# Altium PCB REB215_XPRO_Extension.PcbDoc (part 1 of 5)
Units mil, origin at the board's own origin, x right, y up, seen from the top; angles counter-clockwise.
Board outline 4055.74 x 2606 mil, 6 copper layers (Top Layer LF-signals, Signal Layer 1, Internal Plane 1, Mid-1, Mid-2, Bottom Layer LF-signals), stack 58.434 mil thick; 278 components, 292 nets, 1282 pads, 1177 vias.
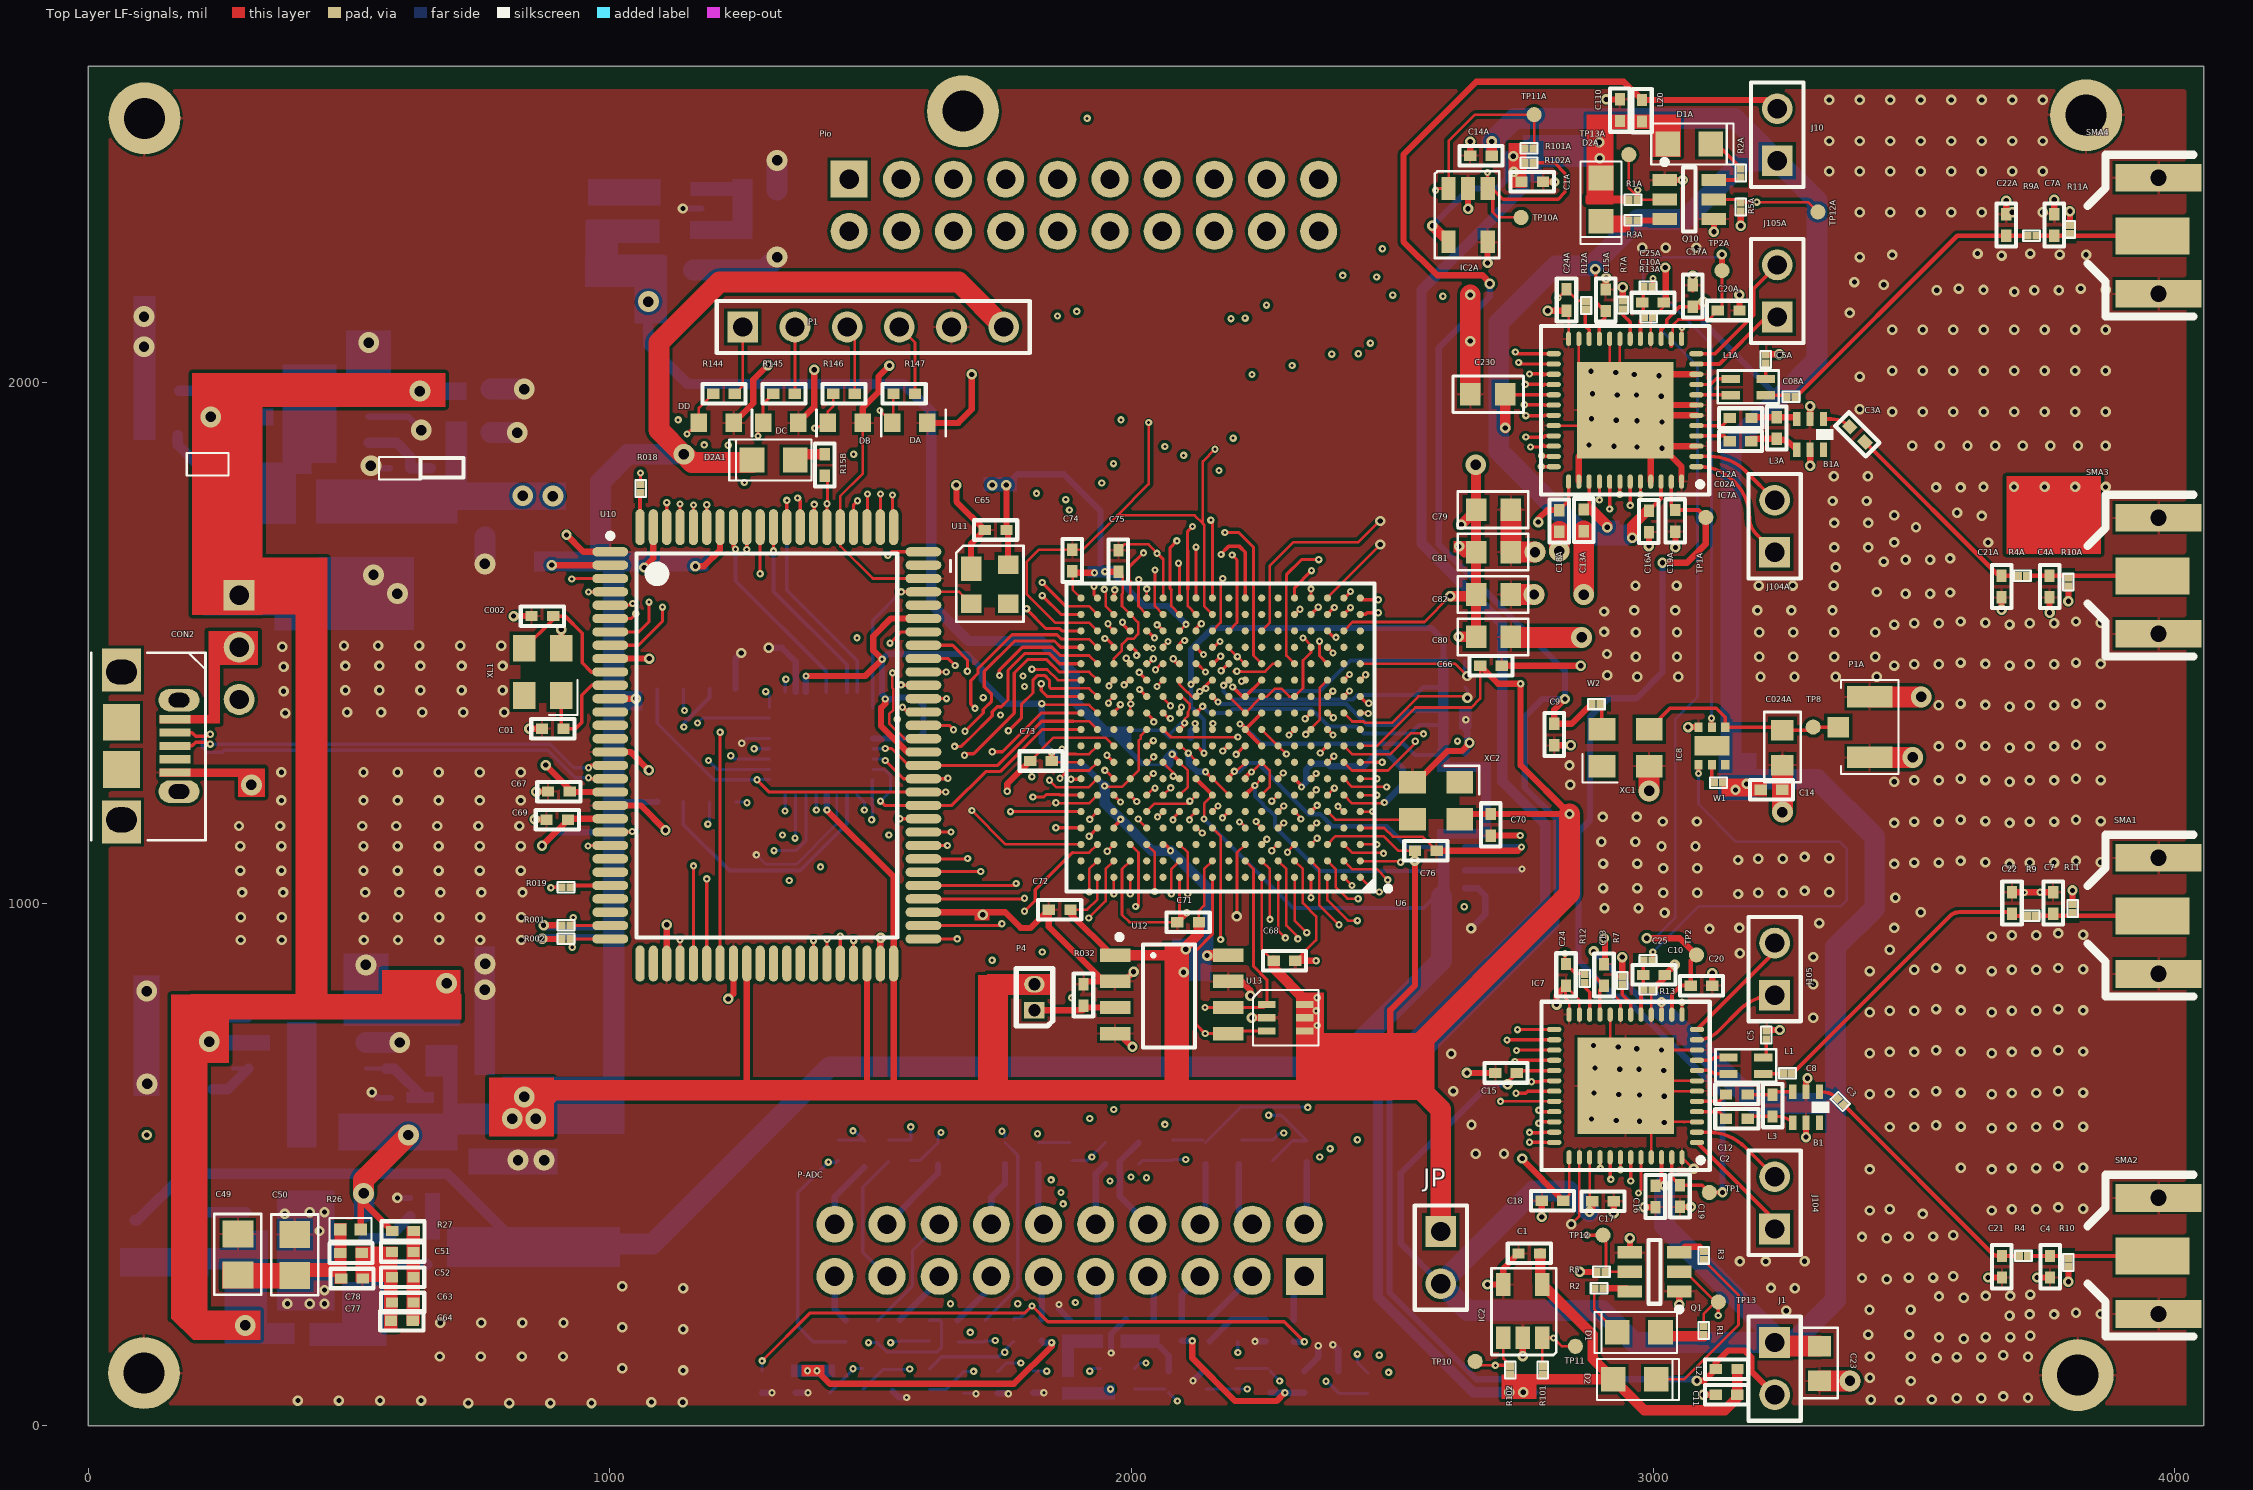
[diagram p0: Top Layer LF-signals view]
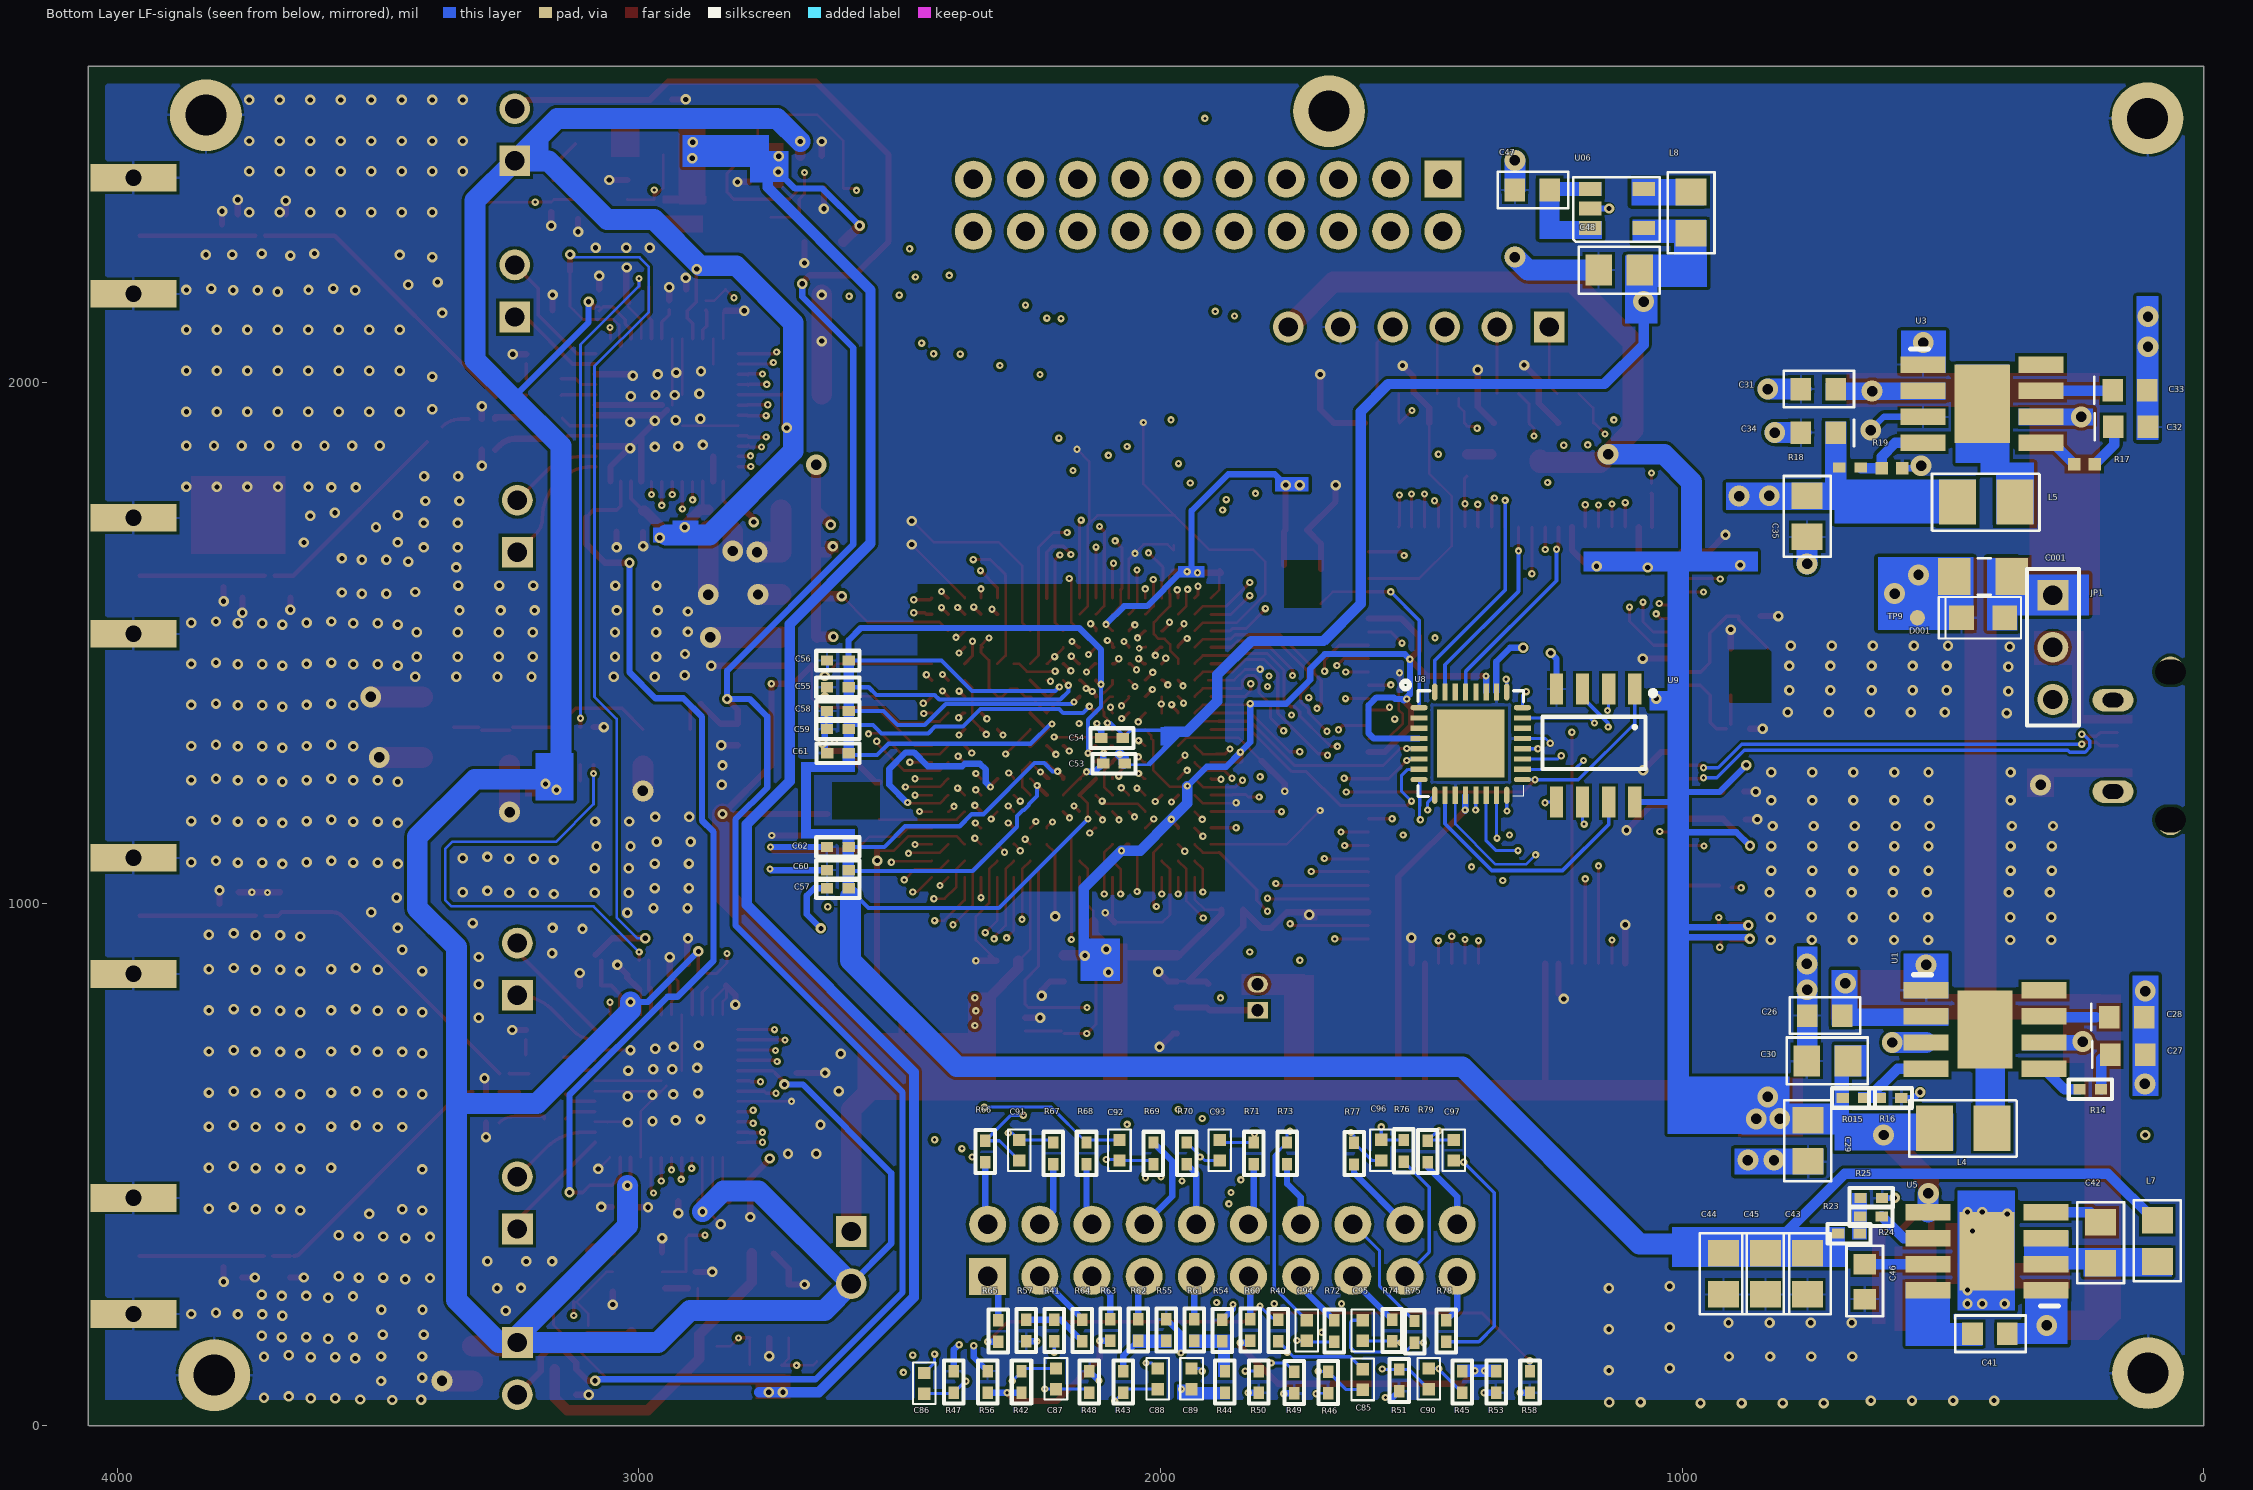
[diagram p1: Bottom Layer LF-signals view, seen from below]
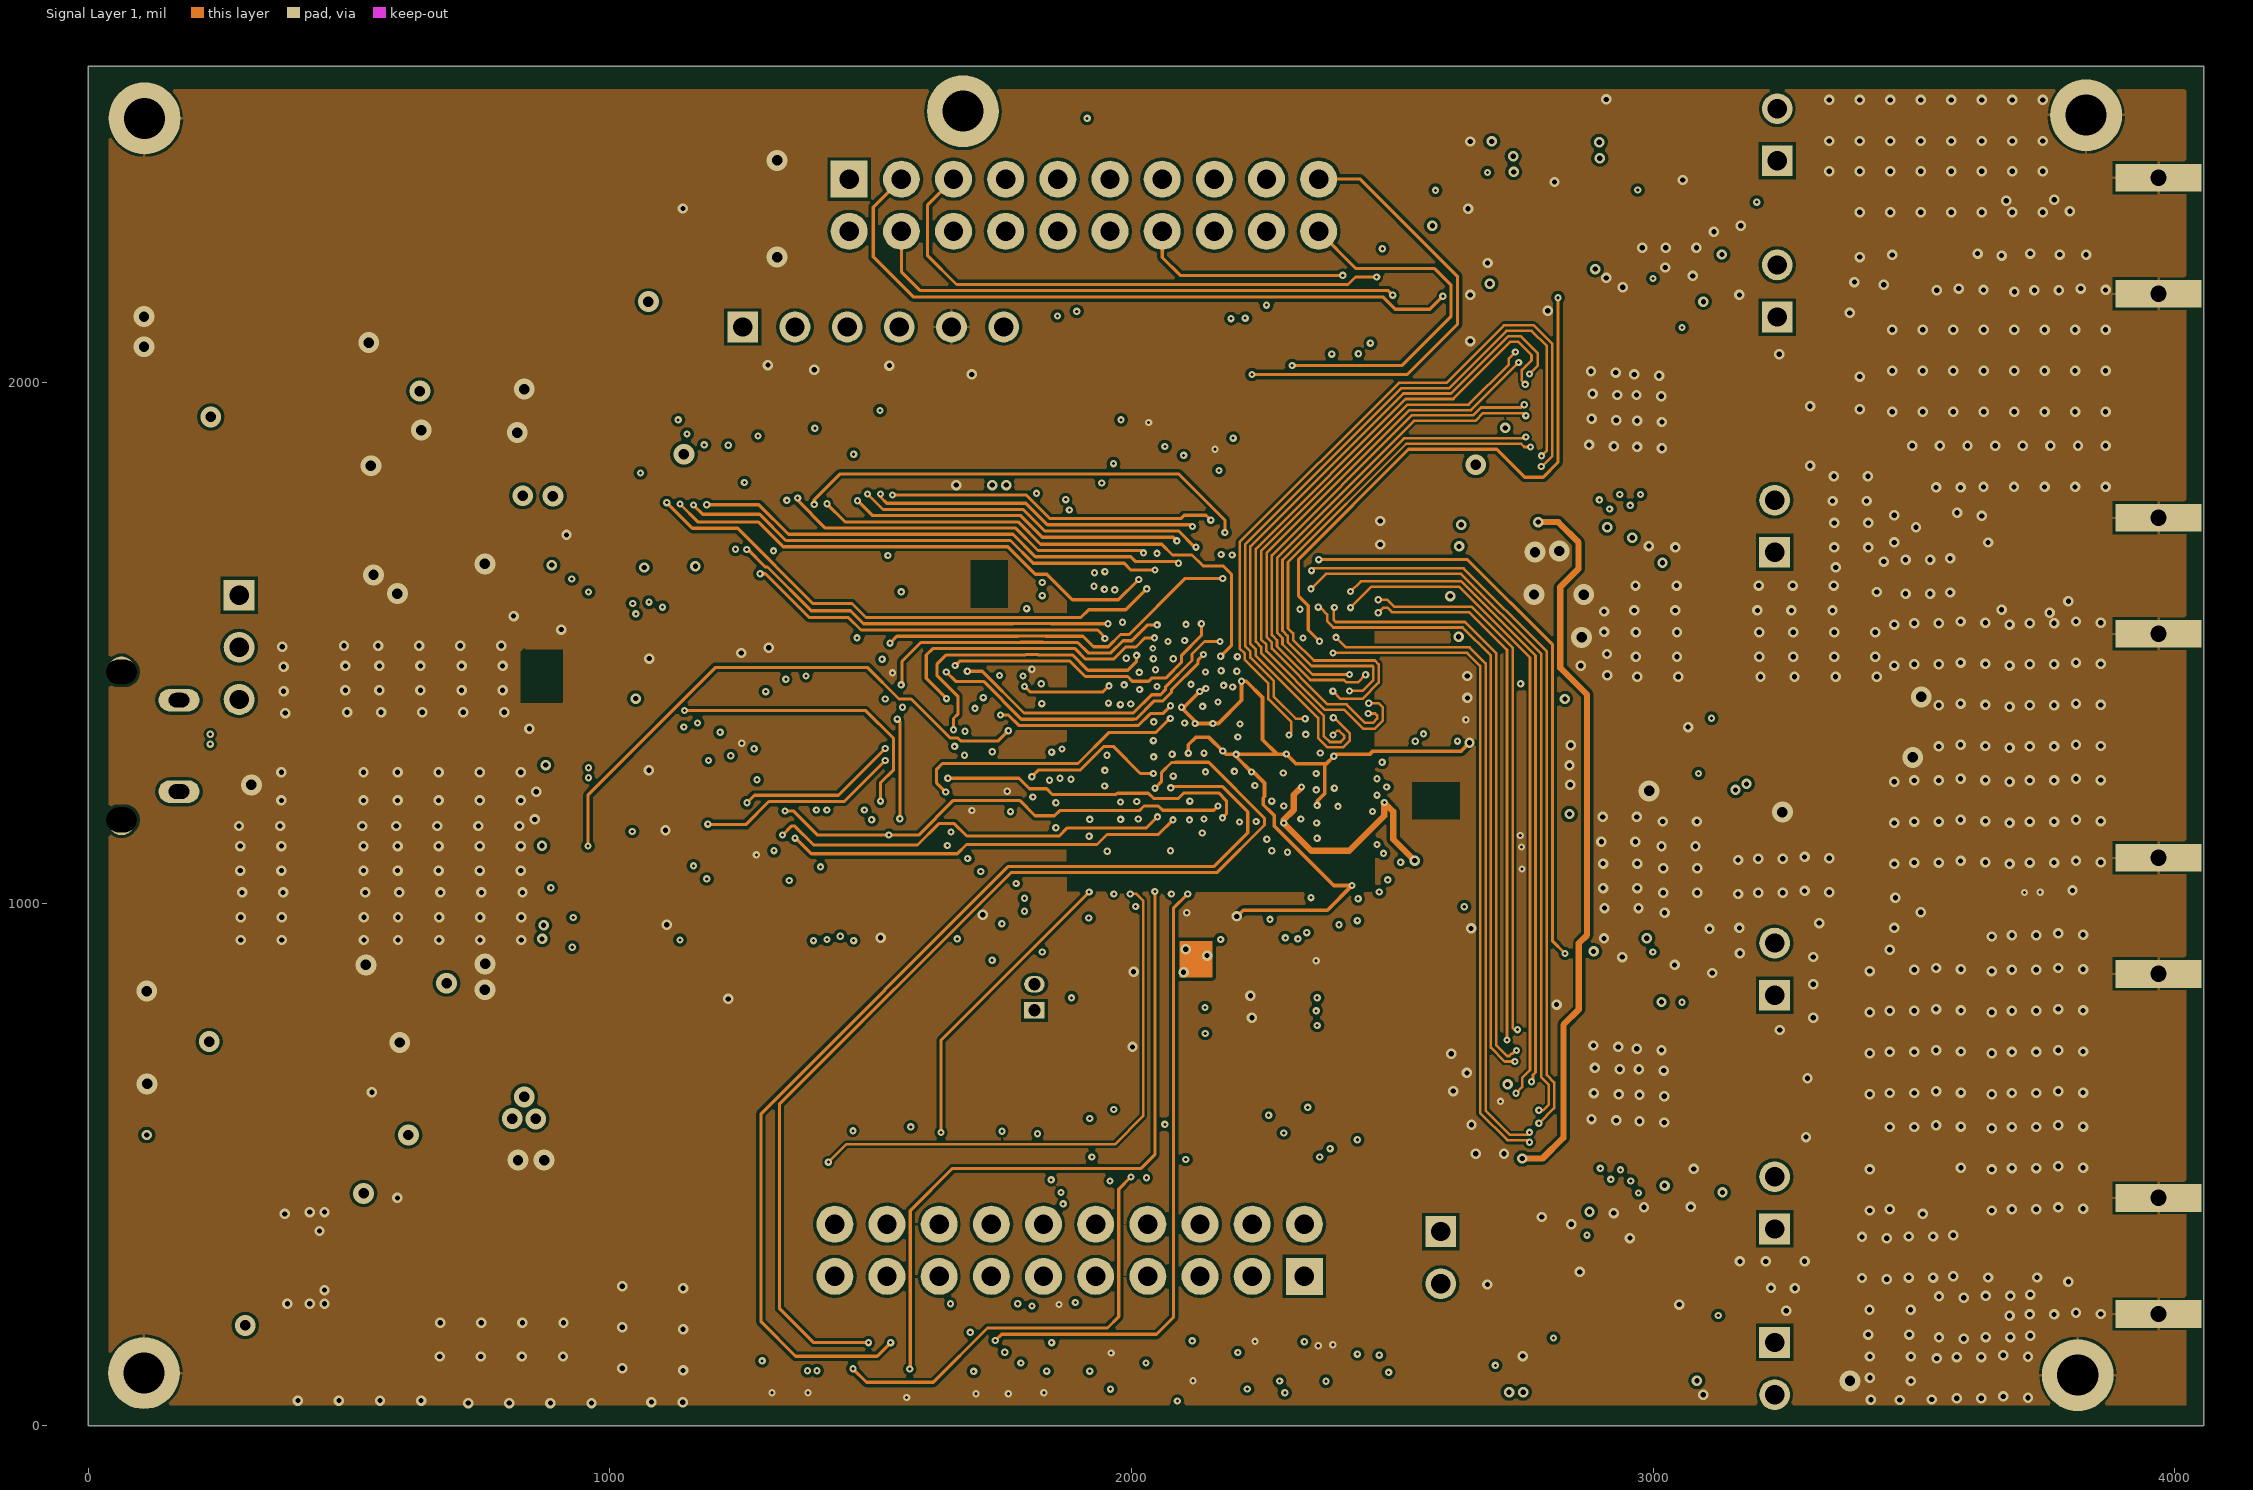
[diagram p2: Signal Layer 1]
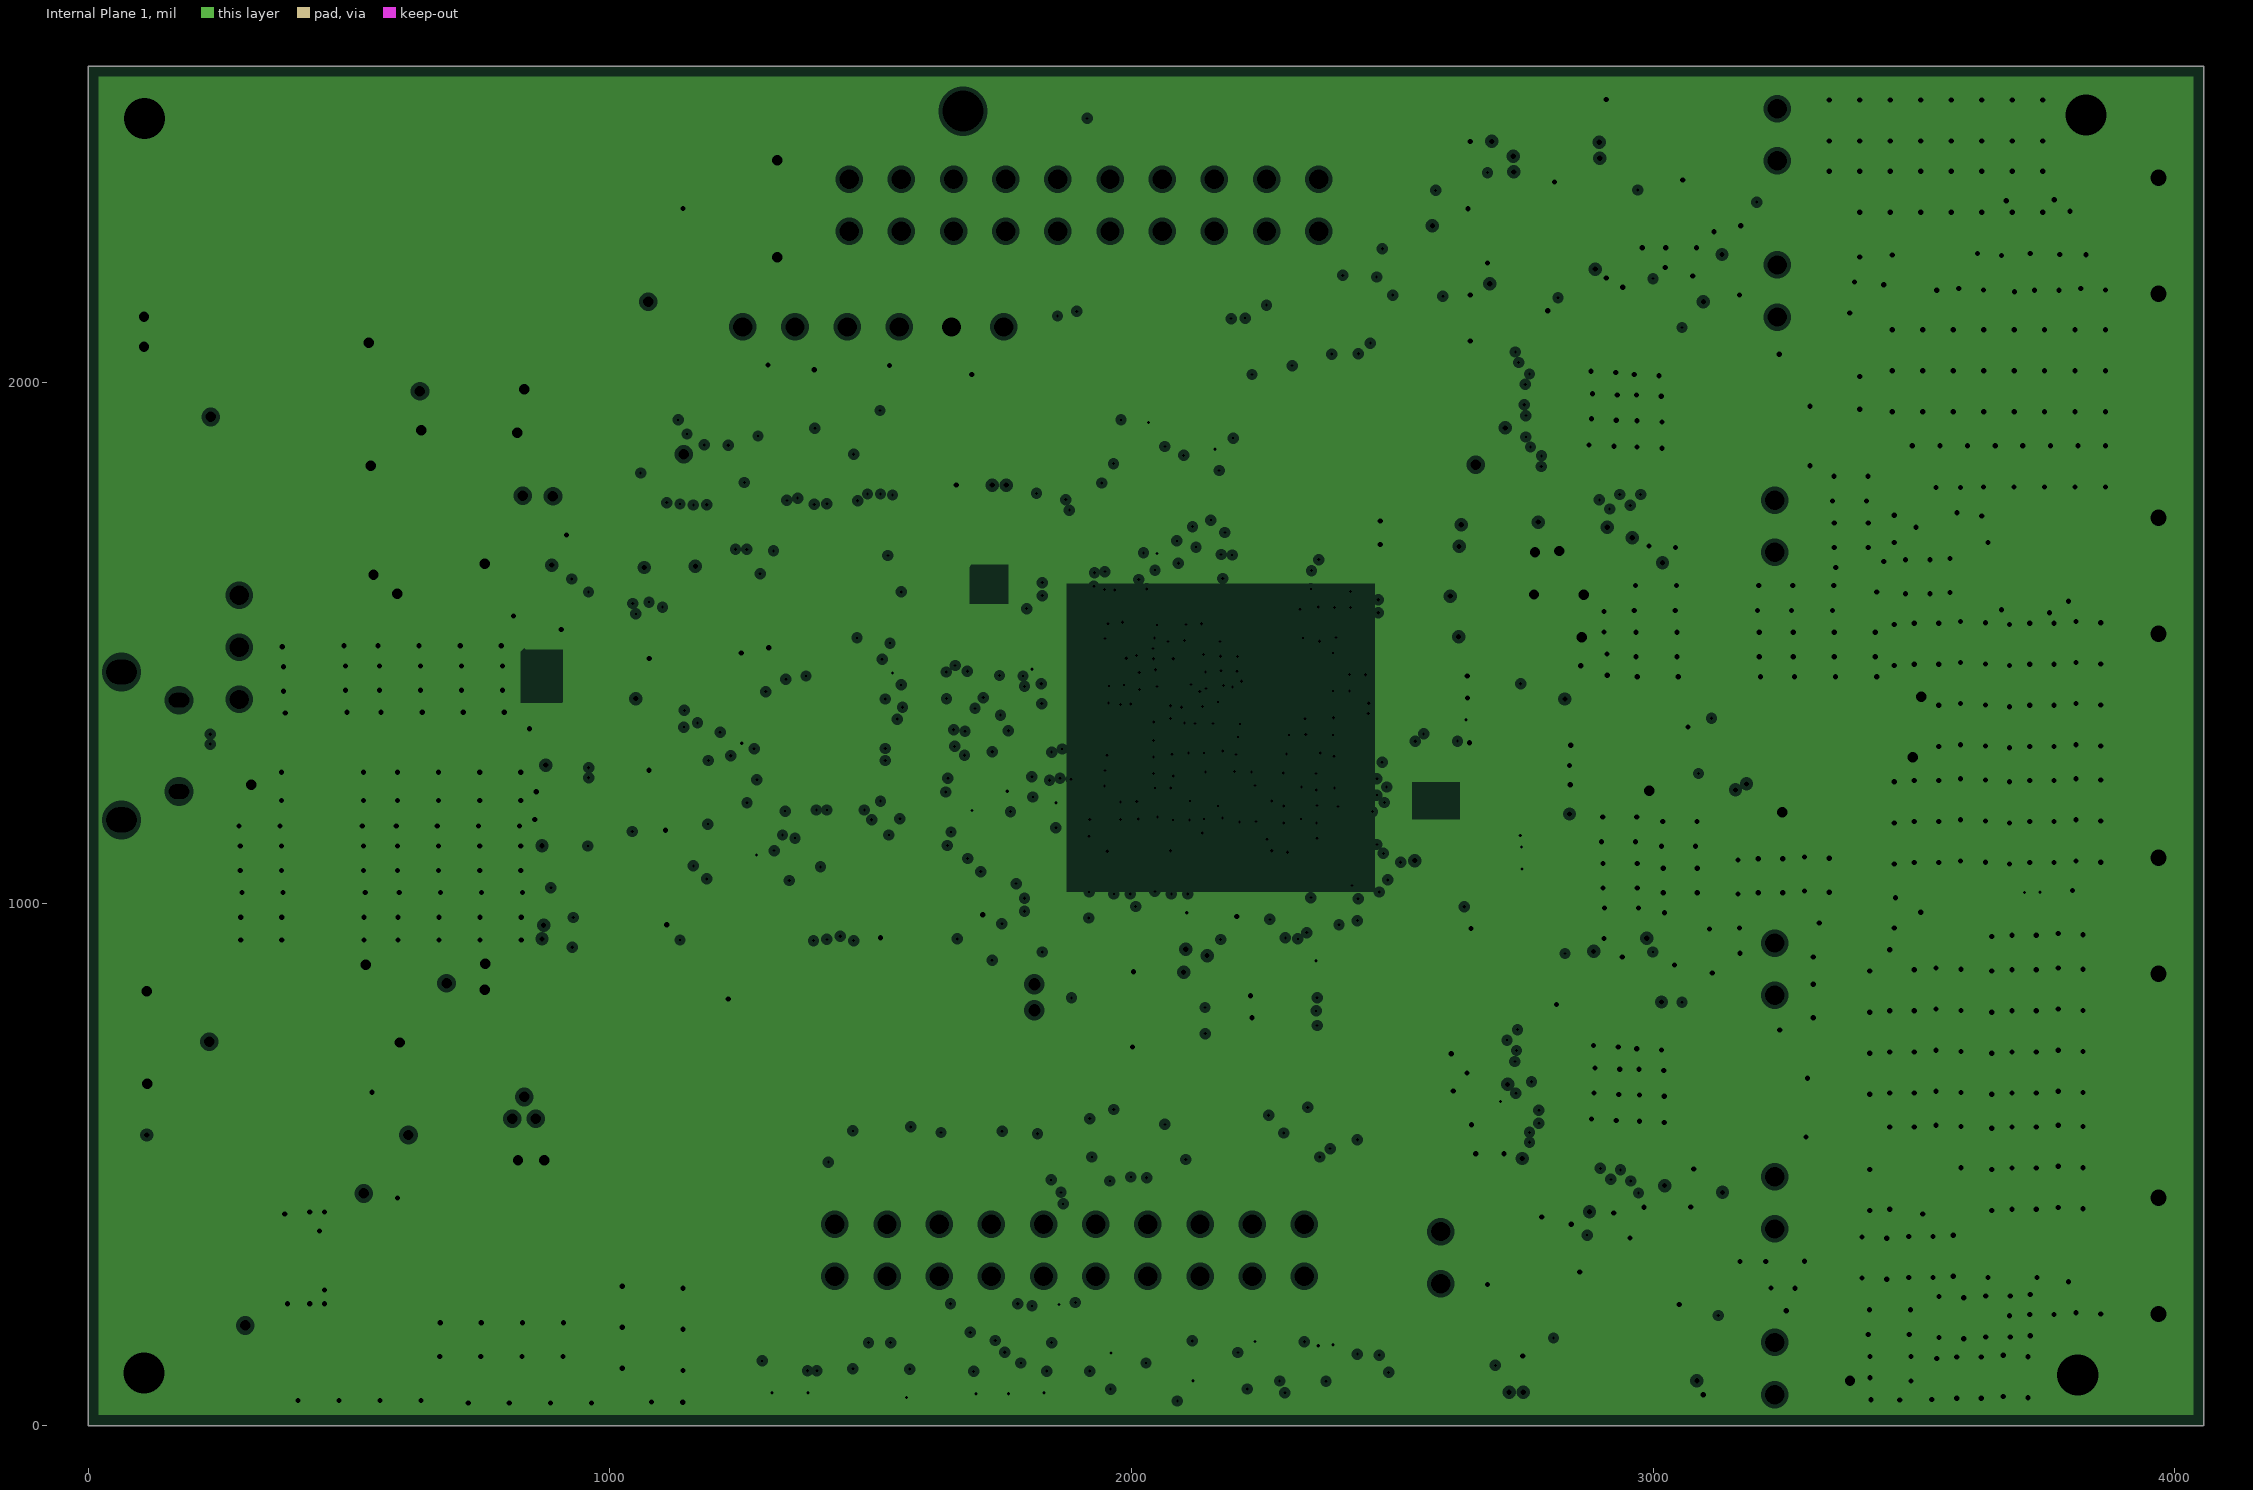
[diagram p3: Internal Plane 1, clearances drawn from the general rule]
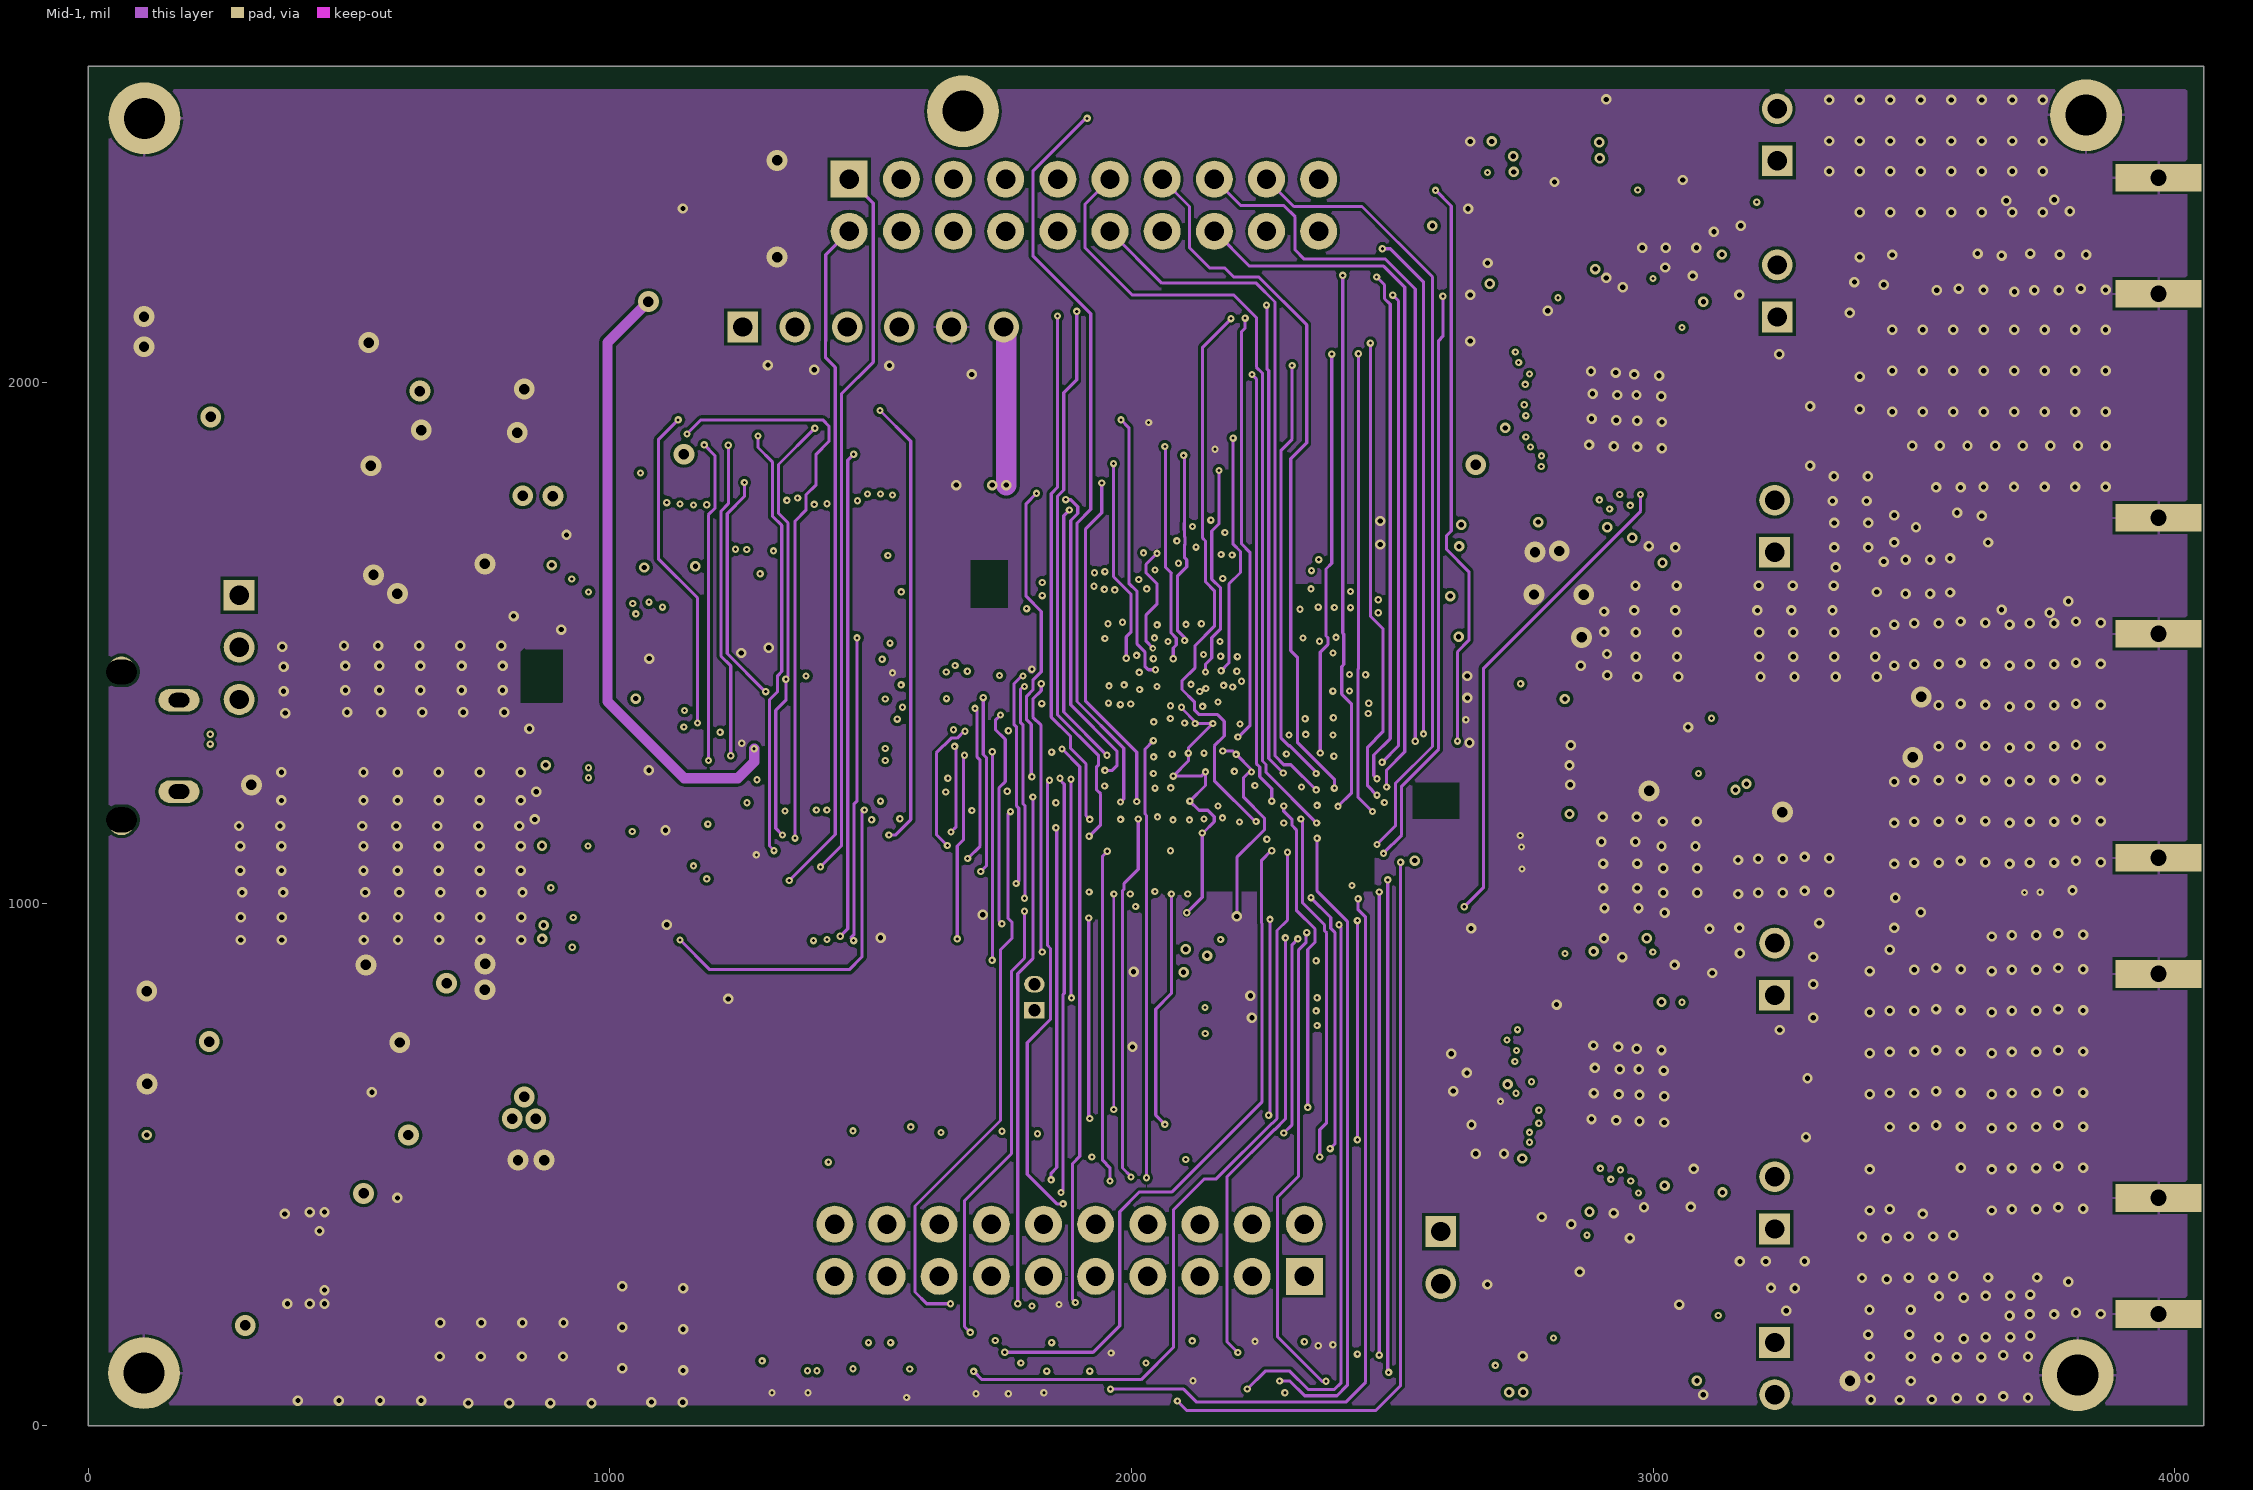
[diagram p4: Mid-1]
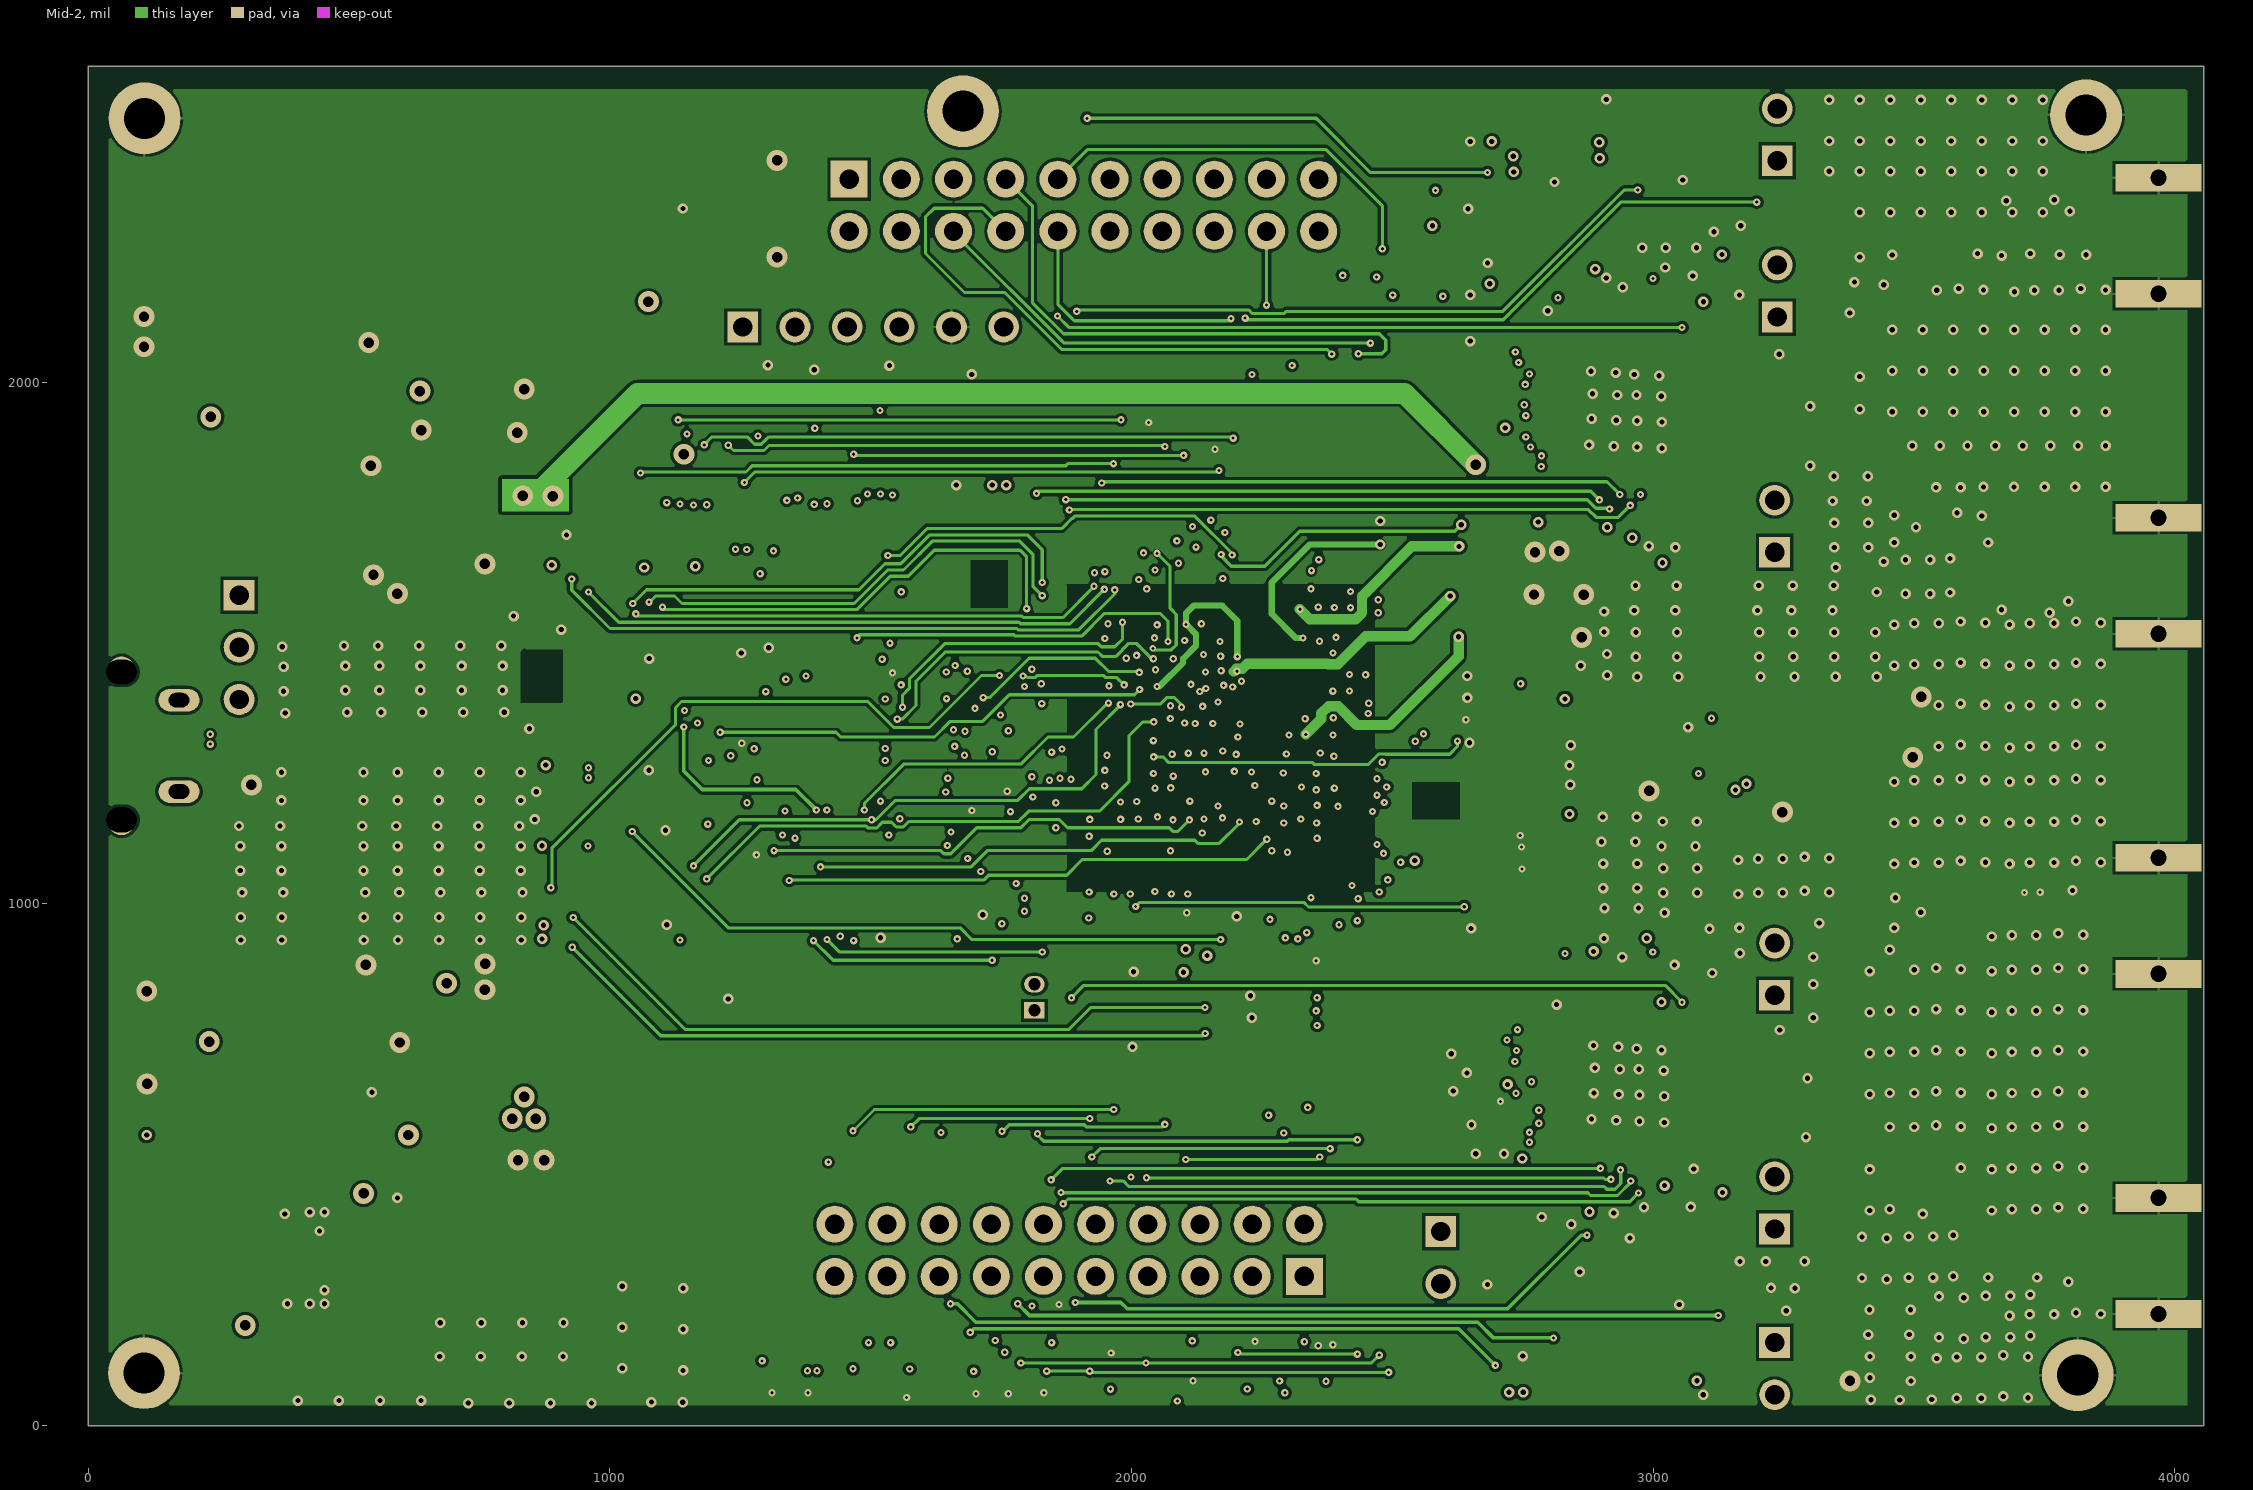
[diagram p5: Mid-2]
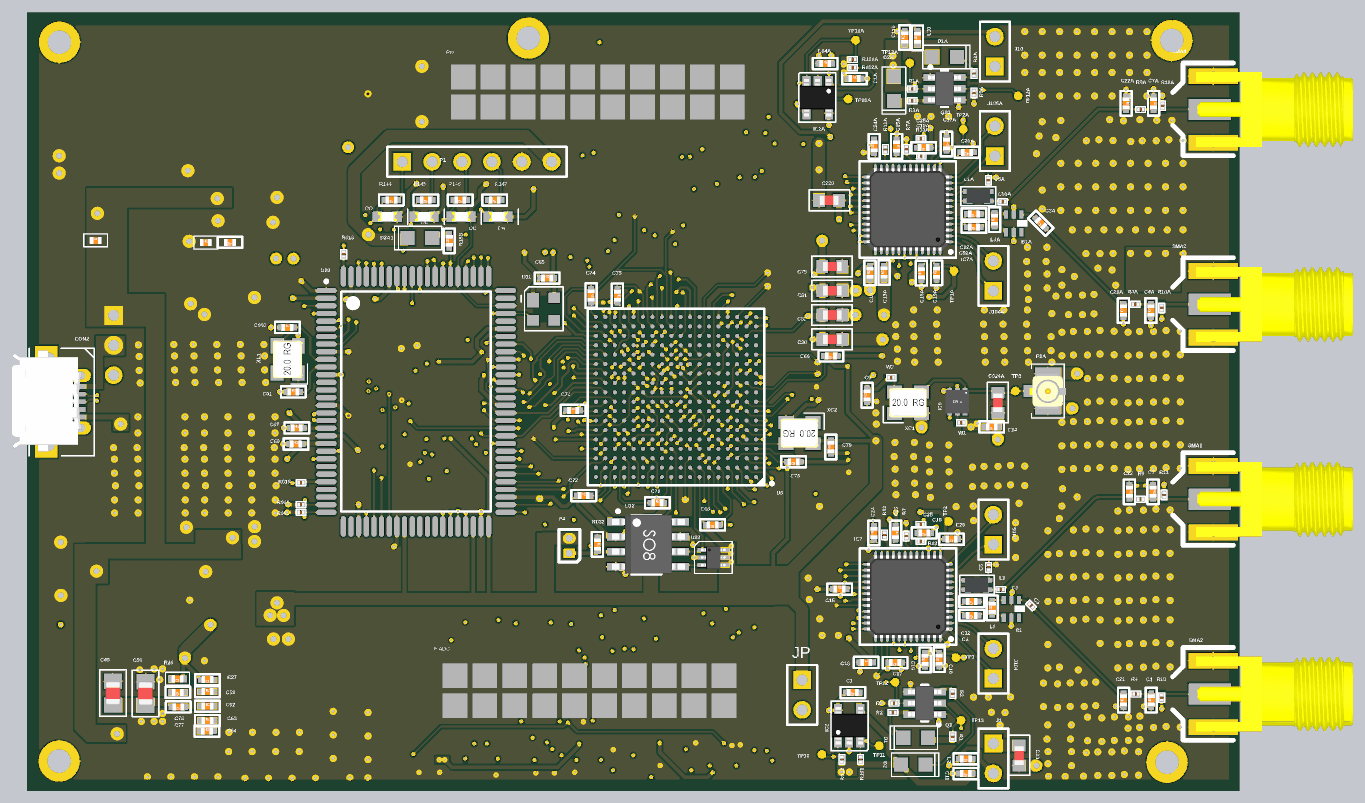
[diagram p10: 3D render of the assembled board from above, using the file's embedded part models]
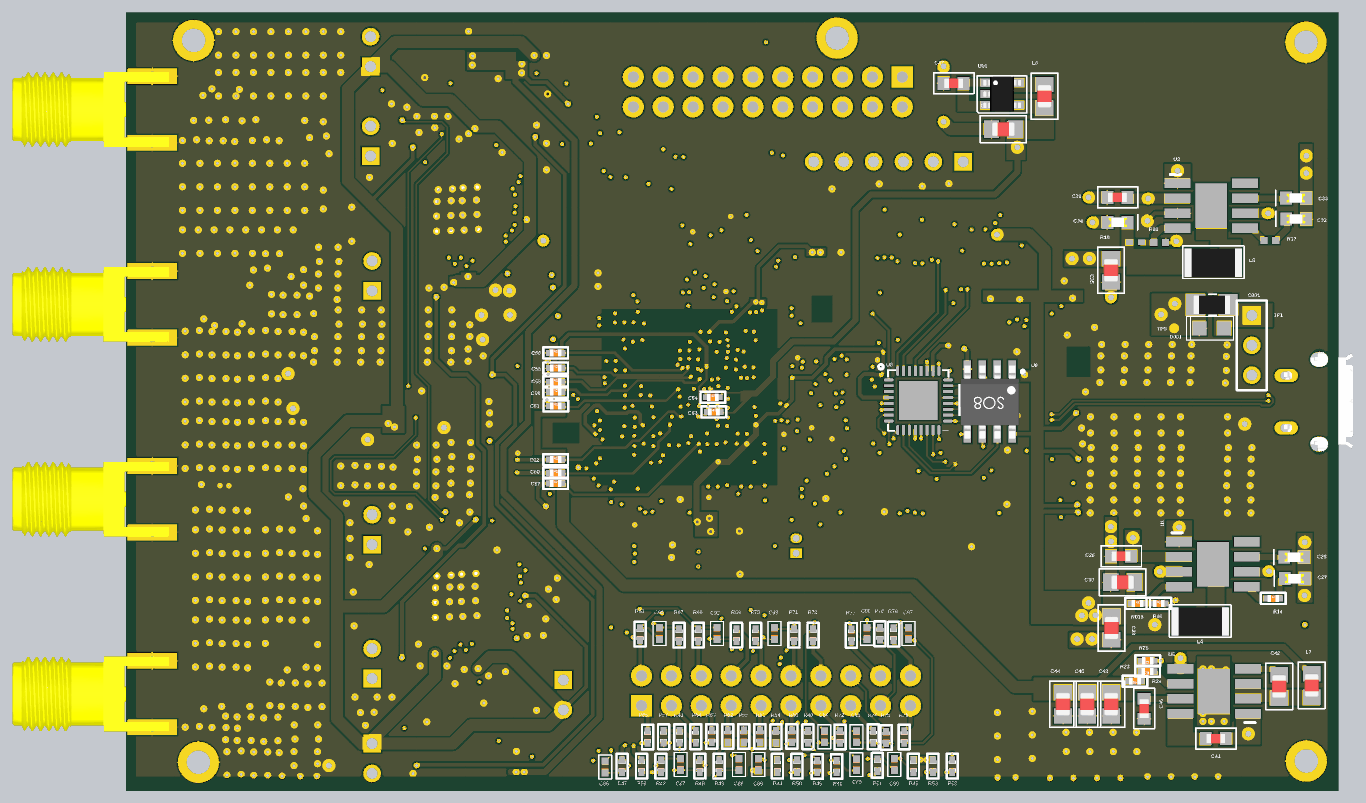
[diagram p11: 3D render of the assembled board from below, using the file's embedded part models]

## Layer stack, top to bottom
Top Solder: solder mask 0.4, Solder Resist, Dk 3.5
Top Layer LF-signals: signal copper 1.4
Dielectric1: core 10, FR-4, Dk 4.2
Signal Layer 1: signal copper 1.417
Dielectric 5: prepreg 10, Dk 4.2
Internal Plane 1: plane copper 1.417, net GND
Dielectric 4: core 10, Dk 4.2
Mid-1: signal copper 1.4
Dielectric2: prepreg 10, FR-4, Dk 4.2
Mid-2: signal copper 1.4
Dielectric3: core 10, FR-4, Dk 4.2
Bottom Layer LF-signals: signal copper 1.4
Bottom Solder: solder mask 0.4, Solder Resist, Dk 3.5

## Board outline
0,0 0,2606 4055.74,2606 4055.74,0.74 4055,0

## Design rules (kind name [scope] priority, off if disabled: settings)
AcuteAngle [All] p1: minimum=0.00000000000000E+0000 checktracksonly=FALSE
AssemblyTestPointUsage [All] p1: allowmultiple=TRUE
AssemblyTestpoint [All] p1: testpointundercomponent=TRUE minsize=31.5 maxsize=393.7 preferedsize=31.5 minholesize=0 maxholesize=78.74 preferedholesize=9.84 testpointgrid=1 usegrid=FALSE gridtolerance=0.01 allowsidebottom=TRUE minspacing=50 compbodyclearance=5
Clearance Clearance_1 [(InDifferentialPairClass('All Differential Pairs'))] p1: gap=5
Clearance Clearance_2 [All] p2: gap=5.91
Clearance Clearance_TP [InComponentClass('TP') vs IsRegion] p3 off: gap=11.81
Clearance Clearance_Poly_Impedance [IsRegion vs (InDifferentialPairClass('All Differential Pairs') OR InNet('NetC22_1') OR InNet('NetC7_1') OR InNet('NetC3_2') OR InNet('NetB1_1') OR InNet('NetC4_1')) OR Innet('netRF24_P') OR InNet('NetC8_2') OR InNet('NetC8_1') OR InNet('NetB1_3') OR InNet('NetB1_4')] p4 off: gap=15.75
Clearance 900Mhz_df [InNet('RF09_P') or InNet('RF09_N') Or InNet('RF24_P') or InNet('RF24_N')] p5: gap=9.84
Clearance Clearance_SPI [InNetClass('SPI') vs InNetClass('SPI')] p6: gap=9.45
Clearance "Stitching GND" [IsStitchingVia and InNet('GND') vs (IsVia and (Not IsStitchingVia)) Or IsPad] p7: gap=7.87
Clearance Clearance_Poly_Impedance_1 [IsRegion vs (InNet('VCC_TARGET') OR InNet('VCC_3V3') OR InNet('NetJ1_1'))] p8 off: gap=11.81
Clearance Clearance_Poly [IsRegion vs (OnLayer('Top Layer LF-signals') OR OnLayer('Bottom Layer LF-signals'))] p9: gap=10
Clearance [All] p10: gap=5.91
DiffPairsRouting [(InDifferentialPairClass('All Differential Pairs'))] p1: maxlimit=5.5 minlimit=5 mostfreqgap=5.5 toplayer_maxgap=5 toplayer_prefgap=5 toplayer_minwidth=6.5 toplayer_maxwidth=6.5 toplayer_prefwidth=6.5 midlayer1_mingap=5.5 midlayer1_minwidth=5 midlayer1_maxwidth=5 midlayer1_prefwidth=5 midlayer2_mingap=5.5 midlayer2_minwidth=5 midlayer2_maxwidth=5 midlayer2_prefwidth=5 midlayer3_mingap=5.5 midlayer3_minwidth=5 midlayer3_maxwidth=5 midlayer3_prefwidth=5 bottomlayer_maxgap=5 bottomlayer_prefgap=5 bottomlayer_minwidth=6.5 bottomlayer_maxwidth=6.5 bottomlayer_prefwidth=6.5 maxuncoupledlength=787.4
FabricationTestPointUsage TestPointUsage [All] p1: valid=0 allowmultiple=TRUE
FabricationTestpoint Testpoint [All] p1: side=2 testpointundercomponent=TRUE minsize=21.65 maxsize=393.7 preferedsize=31.5 minholesize=0 maxholesize=78.74 preferedholesize=9.84 testpointgrid=0 allowsidebottom=TRUE usegrid=FALSE gridtolerance=0.01 minspacing=50 compbodyclearance=5
HoleSize [All] p1: absolutevalues=TRUE maxlimit=393.7 minlimit=5.91 maxpercent=80.000 minpercent=20.000
HoleToHoleClearance [All] p1 off: gap=11.81 allowstackedmicrovias=TRUE
MaxMinImpedance "50ohm Impedance" [InNetClass('50ohm Impedance')] p1: minimum=49.00 maximum=51.00
MinimumAnnularRing MinimumAnnularRing_SATA [InComponentClass('Sata')] p1: minimumring=1.57
MinimumAnnularRing [All] p2: minimumring=3.94
MinimumSolderMaskSliver [All] p1: minsoldermaskwidth=0
PlaneClearance [All] p1: clearance=7.87
PlaneConnect PlaneConnect_VIA [IsVia] p1: planeconnectstyle=Direct reliefexpansion=20 reliefentries=4 reliefconductorwidth=10 reliefairgap=10
PlaneConnect [All] p2: planeconnectstyle=Relief reliefexpansion=20 reliefentries=4 reliefconductorwidth=10 reliefairgap=10
PolygonConnect PolygonConnect_VIA [IsVia OR HasPad('Free-666')] p1: connectstyle=Direct reliefconductorwidth=10 reliefentries=4 polygonreliefangle="90 Angle" airgapwidth=10
PolygonConnect [All] p2: connectstyle=Relief reliefconductorwidth=4.92 reliefentries=4 polygonreliefangle="90 Angle" airgapwidth=4.92
RoutingVias [All] p1: holewidth=10 width=20 viastyle="Through Hole" minholewidth=6 minwidth=12 maxholewidth=20 maxwidth=40
SMDNeckDown [All] p1 off: percent=90.000
SilkToSilkClearance SilkToSilkClearance_Text [IsText vs IsText] p1: silktosilkclearance=0
SilkToSilkClearance [All] p2: silktosilkclearance=3.94
SilkToSolderMaskClearance SilkscreenOverComponentPads [IsPad] p1 off: minsilkscreentomaskgap=0.39 clearancetoexposedcopper=TRUE
SolderMaskExpansion SolderMaskTenting [IsVia AND NOT (IsFabTestpoint OR IsAssyTestpoint)] p1: expansion=-39.37
SolderMaskExpansion [All] p2: expansion=1.97
ViasUnderSMD [All] p1: allowed=FALSE
Width Width_1 [(InDifferentialPairClass('All Differential Pairs'))] p1: maxlimit=10 minlimit=10 preferedwidth=10
Width [All] p2: maxlimit=40 minlimit=5 preferedwidth=12
18 further rules are at their usual default settings.

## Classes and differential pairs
net class NewClass: A-ID_SCL A-ID_SDA A-IRQ A-LED_POWER A-LED_TXRX A-MISO A-MOSI A-R\S\T\N\ A-S\S\_\S\E\L\ A-SCLK ID_SCL ID_SDA IRQ LED_POWER LED_TXRX MISO MOSI R\S\T\N\ S\S\_\S\E\L\ SCL SCLK
net class clk: CLK1 NetC25_1
differential pair RF24A: +RF24A_P -RF24A_N
differential pair RF09A: +RF09A_P -RF09A_N
differential pair RF09: +RF09_P -RF09_N
differential pair B1: +B1_P -B1_N
differential pair RF24: +RF24_P -RF24_N
differential pair AD10: +AD10-P -AD10-N
differential pair TXCLKA: +TXCLKA_P -TXCLKA_N
differential pair TXCLK: +TXCLKP -TXCLKN
differential pair TXDA: +TXDA_P -TXDA_N
differential pair TXD: +TXDP -TXDN
differential pair RXDN09A: +RXDP09A_P -RXDN09A_N
differential pair RXD09: +RXDP09 -RXDN09
differential pair RXCLKA: +RXCLKA_P -RXCLKA_N
differential pair RXCLK: +RXCLKP -RXCLKN
differential pair RXDA24: +RXD24A_P -RXD24A_N
differential pair RXD24: +RXD24P -RXD24N
differential pair usb: +NetCON2_2 -NetCON2_3

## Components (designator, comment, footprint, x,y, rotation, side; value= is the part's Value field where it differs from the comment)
B1 "Balun_2.4GHz" "0805 6pin Balun, narrow variant" 3293.11,610.14 r270 top locked
B1A "Balun_2.4GHz" "0805 6pin Balun, narrow variant" 3301,1900 r270 top locked
C1 "CAP-NONPOL" 0402#1 2742,330 r90 top
C001 "Cap Pol1" 1206-res 423.21,1627.36 r0 bottom locked
C01 "Recommended by Escatec. No datasheet available yet." 0402#1 911.34,1336 r270 top
C1A "CAP-NONPOL" 0402#1 2789,2384.28 r270 top
C2 "CAP-NONPOL" 0402#1 3139.85,588.37 r90 top
C002 "Recommended by Escatec. No datasheet available yet." 0402#1 891.34,1551.81 r270 top
C02A "CAP-NONPOL" 0402#1 3147,1887 r90 top
C3 "CAP-NONPOL" 0201 3359.13,621.02 r315 top locked
C3A "CAP-NONPOL" 0402#1 3377,1914.74 r45 top
C4 "This 1.2pF capacitor is used for RF antennae tuning and can not be replaced by alternatives." 0402#1 3761,325.17 r0 top
C4A "This 1.2pF capacitor is used for RF antennae tuning and can not be replaced by alternatives." 0402#1 3760,1628.95 r0 top
C5 "CAP-NONPOL" 0201 3217,749 r90 top locked
C5A "CAP-NONPOL" 0201 3216,2044.4 r90 top locked
C7 "C0G, NP0" 0402#1 3767,981 r180 top
C7A "C0G, NP0" 0402#1 3769,2281 r180 top
C8 "CAP-NONPOL" 0201 3258,675 r0 top locked
C08A "CAP-NONPOL" 0201 3264.65,1972 r0 top
C9 "CAP-NONPOL" 0402#1 2810.43,1345.34 r0 top
C10 "High Temp version" 0402#1 2980.81,863.95 r90 top
C10A "High Temp version" 0402#1 2979,2153 r90 top
C11 "CAP-NONPOL" 0402#1 3120.09,59 r90 top
C12 "CAP-NONPOL" 0402#1 3139.85,634.83 r90 top
C12A "CAP-NONPOL" 0402#1 3147.19,1931.44 r90 top
C13 "CAP-NONPOL" 0402#1 2905.9,843.34 r180 top
C13A "CAP-NONPOL" 0402#1 2867,1756 r0 top
C14 "CAP-NONPOL" 0402#1 3206.5,1219 r90 top
C14A "CAP-NONPOL" 0402#1 2690.71,2434.37 r270 top
C15 "CAP-NONPOL" 0402#1 2738.91,676 r270 top
C15A "CAP-NONPOL" 0402#1 2909,2136.66 r180 top
C16 "CAP-NONPOL" 0402#1 3004.49,460 r0 top
C16A "CAP-NONPOL" 0402#1 2992,1754 r0 top
C17 "CAP-NONPOL" 0402#1 2883.27,430 r90 top
C17A "CAP-NONPOL" 0402#1 3076,2144.66 r180 top
C18 "CAP-NONPOL" 0402#1 2828,431 r270 top
C18A "CAP-NONPOL" 0402#1 2820,1755 r0 top
C19 "CAP-NONPOL" 0402#1 3051.57,460.57 r0 top
C19A "CAP-NONPOL" 0402#1 3042.7,1755.1 r0 top
C20 "CAP-NONPOL" 0402#1 3072,843.34 r90 top
C20A "CAP-NONPOL" 0402#1 3124.15,2137.65 r90 top
C21 "This 1.2pF capacitor is used for RF antennae tuning and can not be replaced by alternatives." 0402#1 3668.65,325.17 r0 top
C21A "This 1.2pF capacitor is used for RF antennae tuning and can not be replaced by alternatives." 0402#1 3668,1628.95 r0 top
C22 "C0G, NP0" 0402#1 3688,981 r180 top
C22A "C0G, NP0" 0402#1 3677,2280.84 r180 top
C23 "CAP-NONPOL" "0603 - cap" 3319,119 r270 top locked
C24 "CAP-NONPOL" 0402#1 2833,884.72 r0 top
C24A "CAP-NONPOL" 0402#1 2834,2178.32 r0 top
C024A "CAP-NONPOL" "0603 - cap" 3247.84,1299.57 r270 top locked
C25 "CAP-NONPOL" 0201 2990.16,892 r180 top
C25A "CAP-NONPOL" 0201 2990.35,2183 r180 top
C26 "CAP-NONPOL" "0603 - cap" 727,786 r0 bottom
C27 "CAP-NONPOL" "0603 LED"#1 179.12,711 r180 bottom
C28 "CAP-NONPOL" "0603 LED"#1 181,783 r180 bottom
C29 "CAP-NONPOL" "0805 - CAP" 759,546 r90 bottom
C30 "CAP-NONPOL" "0805 - CAP" 721.63,699 r180 bottom
C31 "CAP-NONPOL" "0603 - cap" 739,1986.8 r0 bottom
C32 "CAP-NONPOL" "0603 LED"#1 173.99,1914.4 r180 bottom
C33 "CAP-NONPOL" "0603 LED"#1 174.99,1984.4 r180 bottom
C34 "CAP-NONPOL" "0603 LED"#1 705.54,1903.47 r0 bottom
C35 "CAP-NONPOL" "0805 - CAP" 760.5,1743 r90 bottom
C41 "CAP-NONPOL" "0603 - cap" 410,176 r0 bottom locked
C42 "CAP-NONPOL" "0805 - CAP" 198,350.49 r90 bottom locked
C43 "CAP-NONPOL" "0805 - CAP" 760,291 r90 bottom
C44 "CAP-NONPOL" "0805 - CAP" 921.05,291 r90 bottom
C45 "CAP-NONPOL" "0805 - CAP" 840,291 r90 bottom
C46 "CAP-NONPOL" "0603 - cap" 650,276 r270 bottom locked
C47 "CAP-NONPOL" "0603 - cap" 1287.21,2368.6 r0 bottom
C48 "CAP-NONPOL" "0805 - CAP" 1120.75,2215.05 r180 bottom locked
C49 "Recommended by Escatec. No datasheet available yet." "0805 - CAP" 287,328 r270 top
C50 "Recommended by Escatec. No datasheet available yet." "0805 - CAP" 396,327 r270 top
C51 "Recommended by Escatec. No datasheet available yet." 0402#1 623.67,332.81 r270 top
C52 "Recommended by Escatec. No datasheet available yet." 0402#1 623.67,284.38 r270 top
C53 "Recommended by Escatec. No datasheet available yet." 0402#1 2068.66,1269 r270 bottom
C54 "Recommended by Escatec. No datasheet available yet." 0402#1 2072.23,1318 r270 bottom
C55 "Recommended by Escatec. No datasheet available yet." 0402#1 2598,1415.42 r270 bottom
C56 "Recommended by Escatec. No datasheet available yet." 0402#1 2598,1466.6 r270 bottom
C57 "Recommended by Escatec. No datasheet available yet." 0402#1 2598,1030 r270 bottom
C58 "Recommended by Escatec. No datasheet available yet." 0402#1 2598,1369.87 r270 bottom
C59 "Recommended by Escatec. No datasheet available yet." 0402#1 2598,1335.24 r270 bottom
C60 "Recommended by Escatec. No datasheet available yet." 0402#1 2598,1064.74 r270 bottom
C61 "Recommended by Escatec. No datasheet available yet." 0402#1 2597.66,1289 r270 bottom
C62 "Recommended by Escatec. No datasheet available yet." 0402#1 2598,1109.15 r270 bottom
C63 "Recommended by Escatec. No datasheet available yet." 0402#1 623.67,235.95 r270 top
C64 "Recommended by Escatec. No datasheet available yet." 0402#1 622,201 r270 top
C65 "Recommended by Escatec. No datasheet available yet." 0402#1 1760.34,1716.79 r270 top
C66 "Recommended by Escatec. No datasheet available yet." 0402#1 2668.5,1456.5 r90 top
C67 "Recommended by Escatec. No datasheet available yet." 0402#1 923,1215.4 r270 top
C68 "Recommended by Escatec. No datasheet available yet." 0402#1 2272.66,891 r90 top
C69 "Recommended by Escatec. No datasheet available yet." 0402#1 920,1161.63 r270 top
C70 "Recommended by Escatec. No datasheet available yet." 0402#1 2689,1172.34 r0 top
C71 "Recommended by Escatec. No datasheet available yet." 0402#1 2129.34,965 r270 top
C72 "Recommended by Escatec. No datasheet available yet." 0402#1 1883,989 r270 top
C73 "Recommended by Escatec. No datasheet available yet." 0402#1 1847.34,1274 r270 top
C74 "Recommended by Escatec. No datasheet available yet." 0402#1 1886.73,1637.66 r180 top
C75 "Recommended by Escatec. No datasheet available yet." 0402#1 1975,1636.66 r180 top
C76 "Recommended by Escatec. No datasheet available yet." 0402#1 2543.66,1102.09 r90 top
C77 "Recommended by Escatec. No datasheet available yet." 0402#1 484.88,281.99 r90 top
C78 "Recommended by Escatec. No datasheet available yet." 0402#1 483.33,330.73 r90 top
C79 "Recommended by Escatec. No datasheet available yet." "0603 - cap" 2694,1755.63 r0 top
C80 "Recommended by Escatec. No datasheet available yet." "0603 - cap" 2694,1512 r0 top
C81 "Recommended by Escatec. No datasheet available yet." "0603 - cap" 2694,1674.42 r0 top
C82 "Recommended by Escatec. No datasheet available yet." "0603 - cap" 2694,1593.21 r0 top
C85 "CAP-NONPOL" 0402-res#1 1612.64,88.6 r270 bottom
C86 "CAP-NONPOL" 0402-res#1 2453,81 r270 bottom
C87 "CAP-NONPOL" 0402-res#1 2200.49,89.6 r270 bottom
C88 "CAP-NONPOL" 0402-res#1 2005.53,89.6 r90 bottom
C89 "CAP-NONPOL" 0402-res#1 1940.55,89.6 r90 bottom
C90 "CAP-NONPOL" 0402-res#1 1485.65,89.6 r270 bottom
C91 "" 0402-res#1 2270.95,527.84 r90 bottom
C92 "" 0402-res#1 2078.75,527.84 r270 bottom
C93 "" 0402-res#1 1886.55,527.84 r90 bottom
C94 "" 0402-res#1 1719.84,182.12 r90 bottom
C95 "" 0402-res#1 1612.51,182.12 r90 bottom
C96 "" 0402-res#1 1577,528 r270 bottom
C97 "" 0402-res#1 1438.1,527.84 r90 bottom
C110 "CAP-NONPOL" 0402#1 2936.35,2542.28 r0 top
C230 "CAP-NONPOL" "0603 - cap" 2683,1977 r180 top
CON2 "MICROUSB" MICRO-USB-B-RECEPTABLE 119,1303 r270 top locked
D1 "LED_12" "0805 diode" 2972.77,178.67 r0 top locked
D001 "D Schottky" "0805 diode" 423.21,1548.61 r180 bottom locked
D1A "LED_12" "0805 diode" 3069.32,2456.67 r180 top locked
D2 "LED_12" "0805 diode" 2964.96,88.63 r180 top locked
D2A "LED_12" "0805 diode" 2900.03,2350.37 r90 top locked
D2A1 "LED0" "0805 diode" 1314,1851 r0 top
DA "D Schottky" "0603 LED"#2 1608.69,1922.18 r180 top
DB "D Schottky" "0603 LED"#2 1484.99,1922.18 r180 top
DC "D Schottky" "0603 LED"#2 1361.3,1922.18 r180 top
DD "D Schottky" "0603 LED"#2 1237.6,1922.18 r180 top
IC2 "AT24MAC602" SOT23-5 2750.13,219.28 r0 top locked
IC2A "AT24MAC602" SOT23-5 2645.26,2320.34 r180 top locked
IC7 "48 lead QFN package" "48 pin QFN, 7x7 mm" 2947.24,651.01 r180 top locked
IC7A "48 lead QFN package" "48 pin QFN, 7x7 mm" 2946.24,1946.47 r180 top locked
IC8 "PL133-27" uDFN-6 3112.63,1303 r180 top locked
J1 "HEADER 1x2" HDR1X2 3233,159.3 r270 top locked
J10 "HEADER 1x2" HDR1X2 3238,2424.5 r90 top locked
J104 "HEADER 1x2" HDR1X2 3233,377 r90 top locked
J104A "HEADER 1x2" HDR1X2 3233,1674 r90 top locked
J105 "HEADER 1x2" HDR1X2 3233,825 r90 top locked
J105A "HEADER 1x2" HDR1X2 3238,2125 r90 top locked
JP "HEADER 1x2" HDR1X2 2593,372 r270 top
JP1 "Header 3" HDR1X3 289.35,1591.92 r270 bottom locked
L1 "Common Mode Choke 0805" "DR127 Series Inductor" 3178,690 r180 top locked
L1A "Common Mode Choke 0805" "DR127 Series Inductor" 3182.48,1990.78 r180 top locked
L2 "Inductor_Iron" 0402#1 3120.29,108.32 r90 top
L3 "ceramic chip inductor, 5.6nH, 0201" 0402#1 3229,634 r0 top
L3A "ceramic chip inductor, 5.6nH, 0201" 0402#1 3237,1933 r0 top
L4 "" 1210-RES 461,570 r0 bottom locked
L5 "" 1210-RES 417,1770.4 r0 bottom locked
L7 "" "0805 - CAP" 89,354 r270 bottom locked
L8 "" "0805 - CAP" 982.95,2325.29 r90 bottom locked
L20 "Inductor_Iron" 0402#1 2978.67,2541.3 r0 top
P1 "HDR14" HDR1X6 1255,2106 r0 top
P1A "Copy of A08-0629" AP8-00380 3415.16,1338.94 r270 top locked
P4 "2PHDR" "PIN HEADER 1X2 PIN IN PASTE" 1814,796 r90 top
P-ADC "Header 10X2H" "2x5 Receptacle THM" 1881.41,336 r0 top locked
Pio "GPIO Header" "2x5 Receptacle THM" 1908.95,2339.4 r180 top locked
Q1 "Same as 2N7002 but with two MOSFETs in one package" "SOT23-6 - duplicate" 3002.73,294.59 r180 top locked
Q10 "Same as 2N7002 but with two MOSFETs in one package" "SOT23-6 - duplicate" 3069.32,2350.37 r0 top locked
R1 "R2" 0201 3097,182 r270 top locked
R001 "R2" 0201 916,959 r180 top locked
R1A "R2" 0201 2961.25,2349.72 r180 top locked
R2 "R2" 0201 2896.43,263.1 r180 top locked
R002 "R2" 0201 916,933 r180 top locked
R2A "R2" 0201 3168,2401.35 r90 top locked
R3 "R2" 0201 3097.22,326.09 r270 top locked
R3A "R2" 0201 2961.25,2310.35 r180 top locked
R4 "Copy of A02-0534" 0201 3710,325.17 r0 top locked
R4A "Copy of A02-0534" 0201 3708,1629 r0 top locked
R5 "R2" 0201 2900.37,294.59 r180 top locked
R5A "R2" 0201 3168,2335.97 r270 top locked
R7 "R2" 0201 2941,853.72 r90 top locked
R7A "R2" 0201 2942,2148 r90 top
R9 "Copy of A02-0534" 0201 3725,977.06 r0 top locked
R9A "Copy of A02-0534" 0201 3726,2281 r0 top locked
R10 "Copy of A02-0535" 0201 3796.17,313 r90 top locked
R10A "Copy of A02-0535" 0201 3796.17,1617 r90 top locked
R11 "Copy of A02-0535" 0201 3804,991 r270 top locked
R11A "Copy of A02-0535" 0201 3799,2293 r270 top locked
R12 "R2" 0201 2869,857 r270 top locked
R12A "R2" 0201 2871.44,2146.83 r270 top locked
R13 "Copy of A02-0535" 0201 2990.16,836 r180 top
R13A "Copy of A02-0535" 0201 2991.35,2125 r180 top
R14 "" 0402#1 197.01,645 r270 bottom
R015 "" 0402#1 651,628.01 r270 bottom
R15B "Res1" 0402#1 1412.25,1862 r0 top
R16 "" 0402#1 580.01,628.01 r270 bottom
R17 "" 0402-res#2 229,1843 r180 bottom locked
R018 "R2" 0201 1059,1796.65 r90 top
R18 "" 0402#1 657.8,1836.5 r270 bottom
R019 "R2" 0201 916,1031.91 r180 top locked
R19 "" 0402-res#2 597.8,1835.41 r180 bottom locked
R23 "" 0402#1 658.83,401 r90 bottom
R24 "" 0402#1 701,368 r90 bottom
R25 "" 0402#1 658.34,436.39 r90 bottom
R26 "" 0402-res#1 503,376 r180 top
R27 "" 0402#1 582.66,373 r90 top
R032 "R2" 0402#1 1908,805 r180 top
R40 "Res1" 0402#1 1774.48,161.45 r0 bottom
R41 "Res1" 0402#1 2203.77,161.45 r0 bottom
R42 "Res1" 0402#2 2266.46,104.36 r0 bottom
R43 "Res1" 0402#2 2071.5,63.03 r180 bottom
R44 "Res1" 0402#2 1876.55,63.03 r180 bottom
R45 "Res1" 0402#2 1421.65,63.03 r180 bottom
R46 "Res1" 0402#1 1678.61,103.36 r180 bottom
R47 "Res1" 0402#2 2396.43,63.03 r180 bottom
R48 "Res1" 0402#2 2136.49,63.03 r180 bottom
R49 "Res1" 0402#2 1743.59,103.36 r0 bottom
R50 "Res1" 0402#2 1811.56,104.36 r0 bottom
R51 "Res1" 0402#2 1542.43,107.34 r0 bottom
R53 "Res1" 0402#2 1356.67,63.03 r180 bottom
R54 "Res1" 0402#2 1881.8,202.79 r0 bottom
R55 "Res1" 0402#2 1989.13,203.77 r0 bottom
R56 "Res1" 0402#2 2331.44,104.36 r0 bottom
R57 "Res1" 0402#2 2257.44,161.45 r180 bottom
R58 "Res1" 0402#2 1291.68,63.03 r180 bottom
R60 "Res1" 0402#1 1828.14,162.43 r0 bottom
R61 "Res1" 0402#1 1935.47,162.43 r0 bottom
R62 "Res1" 0402#1 2042.79,162.43 r0 bottom
R63 "Res1" 0402#1 2096.45,162.43 r0 bottom
R64 "Res1" 0402#1 2150.11,161.45 r0 bottom
R65 "Res1" 0402#1 2311.1,160.47 r0 bottom
R66 "" 0402#2 2336,504.66 r180 bottom
R67 "" 0402#2 2205.9,501.27 r180 bottom
R68 "" 0402#2 2141.83,501.27 r180 bottom
R69 "" 0402#2 2013.7,542.61 r0 bottom
R70 "" 0402#2 1949.64,501.27 r180 bottom
R71 "" 0402#2 1821.5,501.27 r180 bottom
R72 "Res1" 0402#2 1667.16,201.81 r0 bottom
R73 "Res1" 0402#2 1757.44,501.27 r180 bottom
R74 "Res1" 0402#2 1556,202.79 r0 bottom
R75 "Res1" 0402#2 1513,200.34 r0 bottom
R76 "Res1" 0402#2 1534,506 r180 bottom
R77 "Res1" 0402#2 1629,500.66 r180 bottom
R78 "Res1" 0402#2 1452.51,201.81 r0 bottom
R79 "Res1" 0402#2 1488,504.66 r180 bottom
R101 "R2" 0201 2788.7,106.02 r270 top locked
R101A "R2" 0201 2761.83,2448.37 r180 top locked
R102 "R2" 0201 2726,106.02 r270 top locked
R102A "R2" 0201 2761.83,2420.7 r180 top locked
R144 "" 0402#1 1198,1978 r90 top
R145 "" 0402#1 1313.22,1978 r90 top
R146 "" 0402#1 1428.44,1978 r90 top
R147 "" 0402#1 1543.66,1978 r90 top
SMA1 "Board Edge Mounting" SMA 3957,977.06 r180 top locked
SMA2 "Board Edge Mounting" SMA 3957,325.17 r180 top locked
SMA3 "Board Edge Mounting" SMA 3957,1628.95 r180 top locked
SMA4 "Board Edge Mounting" SMA 3957,2280.84 r180 top locked
TP1 "TESTPOINT" "Testpad 29 mil" 3107.66,446.94 r90 top locked
TP1A "TESTPOINT" "Testpad 29 mil" 3101,1741 r0 top locked
TP2 "TESTPOINT" "Testpad 29 mil" 3083.07,902.4 r90 top locked
TP2A "TESTPOINT" "Testpad 29 mil" 3132,2214 r90 top locked
TP8 "Mounting hole dia should be 1.6mm. Refer A08-2059" "Testpad 29 mil" 3306.9,1338.94 r0 top locked
TP9 "Mounting hole dia should be 1.6mm. Refer A08-2059" "Testpad 29 mil" 549.2,1548.61 r90 bottom locked
TP10 "TESTPOINT" "Testpad 29 mil" 2659,123 r270 top
TP10A "TESTPOINT" "Testpad 29 mil" 2747,2316 r180 top
TP11 "TESTPOINT" "Testpad 29 mil" 2851,152 r270 top
TP11A "TESTPOINT" "Testpad 29 mil" 2772,2513 r180 top
TP12 "TESTPOINT" "Testpad 29 mil" 2904,365 r90 top locked
TP12A "TESTPOINT" "Testpad 29 mil" 3315.8,2326.62 r90 top locked
TP13 "TESTPOINT" "Testpad 29 mil" 3125,237 r90 top locked
TP13A "TESTPOINT" "Testpad 29 mil" 2953.37,2436.33 r90 top locked
U1 "AOZ1050PI" "so8exposed pad" 419.54,759.4 r270 bottom locked
U3 "AOZ1050PI" "so8exposed pad" 425.06,1958.78 r270 bottom locked
U5 "REG" "so8exposed pad" 415.67,334.18 r90 bottom locked
U06 "IC REG" SOT23-5 1124.68,2333.16 r270 bottom locked
U6 "XC7A35T-2CSG324I" CSG324 2170.92,1318.77 r180 top locked
U8 "CPLD" QFN32_5X5MM_EP3P3MM 1405.35,1307.31 r270 bottom locked
U9 "FLASH" SO8 1091,1412 r270 bottom locked
U10 "CY7C68014A-100AXC" 100qfp 1301,1304 r0 top locked
U11 "STM811" SOT143 1728,1613 r270 top
U12 "128K I 2 C ™ CMOS Serial EEPROM" SO8 1968.83,901.45 r0 top locked
U13 "24AA025E48" sot23-6 2295.95,781.77 r0 top locked
W1 "Jumper" 0201 3125.46,1232.64 r0 top locked
W2 "Jumper" 0201 2890.79,1383.17 r180 top locked
XC1 "TXETCCSANF-26.0000" CRYS 2947.15,1299.57 r0 top
XC2 "TXETCCSANF-26.0000" CRYS 2584,1198 r180 top
XL1 "" CRYS 871.44,1444.71 r90 top locked

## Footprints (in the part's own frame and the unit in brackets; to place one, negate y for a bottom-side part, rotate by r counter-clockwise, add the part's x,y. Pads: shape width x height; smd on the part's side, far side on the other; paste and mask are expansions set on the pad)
"2x5 Receptacle THM" [mm] "2x5 Receptacle THM, Right Angle. No Guide. 2.54mm pitch. Length 13.2mm, width 5.0mm, height 5mm"
  rect 1.8x1.8 hole 0.94: 1(11.43,-1.27)
  round 1.8 hole 0.94: 2(11.43,1.27) 3(8.89,-1.27) 4(8.89,1.27) 5(6.35,-1.27) 6(6.35,1.27) 7(3.81,-1.27) 8(3.81,1.27) 9(1.27,-1.27) 10(1.27,1.27) 11(-1.27,-1.27) 12(-1.27,1.27) 13(-3.81,-1.27) 14(-3.81,1.27) 15(-6.35,-1.27) 16(-6.35,1.27) 17(-8.89,-1.27) 18(-8.89,1.27) 19(-11.43,-1.27) 20(-11.43,1.27)
  rect 2.1x2.1 on Top Paste: 19(-11.43,-1.27) 19(-11.43,1.27) 19(-8.89,-1.27) 19(-8.89,1.27) 19(-6.35,-1.27) 19(-6.35,1.27) 19(-3.81,-1.27) 19(-3.81,1.27) 19(-1.27,-1.27) 19(-1.27,1.27) 19(1.27,-1.27) 19(1.27,1.27) 19(3.81,-1.27) 19(3.81,1.27) 19(6.35,-1.27) 19(6.35,1.27) 19(8.89,-1.27) 19(8.89,1.27) 19(11.43,-1.27) 19(11.43,1.27)
"48 pin QFN, 7x7 mm" [mm] "48 pin QFN, 7x7 mm"
  oval 0.7x0.25 smd: 1(-3.475,2.75) 2(-3.475,2.25) 3(-3.475,1.75) 4(-3.475,1.25) 5(-3.475,0.75) 6(-3.475,0.25) 7(-3.475,-0.25) 8(-3.475,-0.75) 9(-3.475,-1.25) 10(-3.475,-1.75) 11(-3.475,-2.25) 12(-3.475,-2.75) 25(3.475,-2.75) 26(3.475,-2.25) 27(3.475,-1.75) 28(3.475,-1.25) 29(3.475,-0.75) 30(3.475,-0.25) 31(3.475,0.25) 32(3.475,0.75) 33(3.475,1.25) 34(3.475,1.75) 35(3.475,2.25) 36(3.475,2.75)
  rect 4.7x1.4 on Top Solder: 4.8(0,-1) 14(0,1)
  rrect50% 1.65x1.65 on Top Paste: 10(-1,1) 11(-1,-1) 12(1.025,-0.975) 13(1,1)
  oval 0.25x0.7 smd: 13(-2.75,-3.475) 14(-2.25,-3.475) 15(-1.75,-3.475) 16(-1.25,-3.475) 17(-0.75,-3.475) 18(-0.25,-3.475) 19(0.25,-3.475) 20(0.75,-3.475) 21(1.25,-3.475) 22(1.75,-3.475) 23(2.25,-3.475) 24(2.75,-3.475) 37(2.75,3.475) 38(2.25,3.475) 39(1.75,3.475) 40(1.25,3.475) 41(0.75,3.475) 42(0.25,3.475) 43(-0.25,3.475) 44(-0.75,3.475) 45(-1.25,3.475) 46(-1.75,3.475) 47(-2.25,3.475) 48(-2.75,3.475)
  rect 1.4x4.7 on Top Solder: 16(-1,0) 17(1,0)
  rect 4.7x4.7 smd paste-5.2 mask-5.2: 49(0,0)
  silkscreen extent -4.1,-4.1 4.1,4.1, body extent -3.5,-3.5 3.5,3.5, height 0.91
100qfp [mm] "100-Pin Thin Plastic Quad Flat Pack Rectangular 0.65 mm Pitch, IPC Medium Density"
  oval 1.75x0.45 smd: 1(-7.625,9.425) 2(-7.625,8.775) 3(-7.625,8.125) 4(-7.625,7.475) 5(-7.625,6.825) 6(-7.625,6.175) 7(-7.625,5.525) 8(-7.625,4.875) 9(-7.625,4.225) 10(-7.625,3.575) 11(-7.625,2.925) 12(-7.625,2.275) 13(-7.625,1.625) 14(-7.625,0.975) 15(-7.625,0.325) 16(-7.625,-0.325) 17(-7.625,-0.975) 18(-7.625,-1.625) 19(-7.625,-2.275) 20(-7.625,-2.925) 21(-7.625,-3.575) 22(-7.625,-4.225) 23(-7.625,-4.875) 24(-7.625,-5.525) 25(-7.625,-6.175) 26(-7.625,-6.825) 27(-7.625,-7.475) 28(-7.625,-8.125) 29(-7.625,-8.775) 30(-7.625,-9.425) 51(7.625,-9.425) 52(7.625,-8.775) 53(7.625,-8.125) 54(7.625,-7.475) 55(7.625,-6.825) 56(7.625,-6.175) 57(7.625,-5.525) 58(7.625,-4.875) 59(7.625,-4.225) 60(7.625,-3.575) 61(7.625,-2.925) 62(7.625,-2.275) 63(7.625,-1.625) 64(7.625,-0.975) 65(7.625,-0.325) 66(7.625,0.325) 67(7.625,0.975) 68(7.625,1.625) 69(7.625,2.275) 70(7.625,2.925) 71(7.625,3.575) 72(7.625,4.225) 73(7.625,4.875) 74(7.625,5.525) 75(7.625,6.175) 76(7.625,6.825) 77(7.625,7.475) 78(7.625,8.125) 79(7.625,8.775) 80(7.625,9.425)
  oval 0.45x1.75 smd: 31(-6.175,-10.625) 32(-5.525,-10.625) 33(-4.875,-10.625) 34(-4.225,-10.625) 35(-3.575,-10.625) 36(-2.925,-10.625) 37(-2.275,-10.625) 38(-1.625,-10.625) 39(-0.975,-10.625) 40(-0.325,-10.625) 41(0.325,-10.625) 42(0.975,-10.625) 43(1.625,-10.625) 44(2.275,-10.625) 45(2.925,-10.625) 46(3.575,-10.625) 47(4.225,-10.625) 48(4.875,-10.625) 49(5.525,-10.625) 50(6.175,-10.625) 81(6.175,10.625) 82(5.525,10.625) 83(4.875,10.625) 84(4.225,10.625) 85(3.575,10.625) 86(2.925,10.625) 87(2.275,10.625) 88(1.625,10.625) 89(0.975,10.625) 90(0.325,10.625) 91(-0.325,10.625) 92(-0.975,10.625) 93(-1.625,10.625) 94(-2.275,10.625) 95(-2.925,10.625) 96(-3.575,10.625) 97(-4.225,10.625) 98(-4.875,10.625) 99(-5.525,10.625) 100(-6.175,10.625)
  silkscreen extent -7.75,-9.35 6.35,10.32, body extent -7,-10 7,10, height 1.6
0201 [mil] "0201_SMD"
  rect 17x15.09 smd paste+0 mask+2.49: 1(-9.35,0) 2(9.35,0)
  silkscreen extent -16,-10 16,10, body extent -12,-6 12,6, height 12
0402#1 [mm] "Generic pad 0402, spacing 0.45mm"
  rect 0.5x0.6 smd: 1(0,0) 2(0,-1.05)
  silkscreen extent -0.48,-1.58 0.48,0.53, body extent -0.3,-1.02 0.3,-0.03, height 0.2
0402#2 [mm] "Generic pad 0402, spacing 0.45mm"
  rect 0.5x0.6 smd: 1(0,0) 2(0,1.05)
  silkscreen extent -0.48,-0.53 0.48,1.58, body extent -0.3,0.02 0.3,1.02
0402-res#1 [mm] "Standard 0402 SMD capacitor footprint"
  rect 0.6x0.6 smd: 1(-0.5,0) 2(0.5,0)
  silkscreen extent -1.02,-0.55 1.02,0.55, body extent -0.5,-0.3 0.5,0.3
0402-res#2 [mm] "Standard 0402 SMD capacitor footprint"
  rect 0.6x0.6 smd: 1(0.5,0) 2(-0.5,0)
  body extent -0.5,-0.3 0.5,0.3, height 0.2
"0603 - cap" [mm] "CAPC0603M"
  rect 1x1.1 smd mask+0.051: 1(-0.85,0) 2(0.85,0)
  silkscreen extent -1.74,-0.89 1.69,0.89, body extent -0.8,-0.4 0.8,0.4, height 0.3
"0603 LED"#1 [mm] "0603"
  rect 1x1.1 smd mask+0.051: 1(0,0) 2(1.7,0)
  silkscreen extent -0.89,-0.63 -0.89,0.66, body extent 0.02,-0.39 1.62,0.39, height 0.7
"0603 LED"#2 [mm] "0603"
  rect 0.8x0.9 smd mask+0.051: 1(0,0) 2(1.7,0)
  silkscreen extent -0.89,-0.64 -0.89,0.66, body extent 0.02,-0.39 1.62,0.39, height 0.7
"0805 6pin Balun, narrow variant" [mm] "0805 6pin Balun, narrow variant"
  rect 0.7x0.35 smd: 1(-0.75,0.65) 2(-0.75,0) 3(-0.75,-0.65) 4(0.75,-0.65) 5(0.75,0) 6(0.75,0.65)
  silkscreen extent -0.27,0.28 0.28,1.15, body extent -0.65,-0.95 0.6,1, height 0.85
"0805 - CAP" [mm] "CAPC2012N"
  rect 1.3x1.5 smd: 1(1,0) 2(-1,0)
  silkscreen extent -1.97,-1.14 1.97,1.14, body extent -1,-0.62 1,0.63, height 0.78
"0805 diode" [mm] "0805 diode footprint"
  rect 1.2x1.2 smd: 1(-1.05,0) 2(1.05,0)
  silkscreen extent -2.16,-1 1.85,1, body extent -1,-0.63 1,0.63, height 1.1
1206-res [mm] "Chip Capacitor, Body 3.2x1.6mm, IPC High Density"
  rect 1.6x1.8 smd: 1(-1.4,0) 2(1.4,0)
  silkscreen extent -0.38,-0.89 0.25,0.89, body extent -1.55,-0.77 1.55,0.78, height 0.55
1210-RES [mm]
  rect 1.8x2.2 smd: 1(-1.4,0) 2(1.4,0)
  silkscreen extent -2.59,-1.37 2.64,1.4, body extent -2.41,-1.14 2.49,1.26, height 0.55
AP8-00380 [mm]
  rect 1x1.05 smd: 1(0,-1.525)
  rect 1.05x2.2 smd: 2(-1.475,0) 3(1.475,0)
  silkscreen extent -2.29,-1.4 2.29,1.4, body extent -1.48,-1.55 1.52,1.55, height 1.23
CRYS [mm] "Geyer KX-7 Crystal 3.2X2"
  rect 1.3x1.1 smd: 1(-1.15,-0.9) 2(1.15,-0.9) 3(1.15,0.9) 4(-1.15,0.9)
  silkscreen extent -2.1,-1.7 -0.4,-0.3, body extent -1.61,-1.25 1.61,1.25, height 0.82
CSG324 [mm] "BGA, 324-Balls, Body 15x15mm, Pitch 0.8mm"
  round 0.35 smd: A1(-6.8,6.8) A2(-6,6.8) A3(-5.2,6.8) A4(-4.4,6.8) A5(-3.6,6.8) A6(-2.8,6.8) A7(-2,6.8) A8(-1.2,6.8) A9(-0.4,6.8) A10(0.4,6.8) A11(1.2,6.8) A12(2,6.8) A13(2.8,6.8) A14(3.6,6.8) A15(4.4,6.8) A16(5.2,6.8) A17(6,6.8) A18(6.8,6.8) B1(-6.8,6) B2(-6,6) B3(-5.2,6) B4(-4.4,6) B5(-3.6,6) B6(-2.8,6) B7(-2,6) B8(-1.2,6) B9(-0.4,6) B10(0.4,6) B11(1.2,6) B12(2,6) B13(2.8,6) B14(3.6,6) B15(4.4,6) B16(5.2,6) B17(6,6) B18(6.8,6) C1(-6.8,5.2) C2(-6,5.2) C3(-5.2,5.2) C4(-4.4,5.2) C5(-3.6,5.2) C6(-2.8,5.2) C7(-2,5.2) C8(-1.2,5.2) C9(-0.4,5.2) C10(0.4,5.2) C11(1.2,5.2) C12(2,5.2) C13(2.8,5.2) C14(3.6,5.2) C15(4.4,5.2) C16(5.2,5.2) C17(6,5.2) C18(6.8,5.2) D1(-6.8,4.4) D2(-6,4.4) D3(-5.2,4.4) D4(-4.4,4.4) D5(-3.6,4.4) D6(-2.8,4.4) D7(-2,4.4) D8(-1.2,4.4) D9(-0.4,4.4) D10(0.4,4.4) D11(1.2,4.4) D12(2,4.4) D13(2.8,4.4) D14(3.6,4.4) D15(4.4,4.4) D16(5.2,4.4) D17(6,4.4) D18(6.8,4.4) E1(-6.8,3.6) E2(-6,3.6) E3(-5.2,3.6) E4(-4.4,3.6) E5(-3.6,3.6) E6(-2.8,3.6) E7(-2,3.6) E8(-1.2,3.6) E9(-0.4,3.6) E10(0.4,3.6) E11(1.2,3.6) E12(2,3.6) E13(2.8,3.6) E14(3.6,3.6) E15(4.4,3.6) E16(5.2,3.6) E17(6,3.6) E18(6.8,3.6) F1(-6.8,2.8) F2(-6,2.8) F3(-5.2,2.8) F4(-4.4,2.8) F5(-3.6,2.8) F6(-2.8,2.8) F7(-2,2.8) F8(-1.2,2.8) F9(-0.4,2.8) F10(0.4,2.8) F11(1.2,2.8) F12(2,2.8) F13(2.8,2.8) F14(3.6,2.8) F15(4.4,2.8) F16(5.2,2.8) F17(6,2.8) F18(6.8,2.8) G1(-6.8,2) G2(-6,2) G3(-5.2,2) G4(-4.4,2) G5(-3.6,2) G6(-2.8,2) G7(-2,2) G8(-1.2,2) G9(-0.4,2) G10(0.4,2) G11(1.2,2) G12(2,2) G13(2.8,2) G14(3.6,2) G15(4.4,2) G16(5.2,2) G17(6,2) G18(6.8,2) H1(-6.8,1.2) H2(-6,1.2) H3(-5.2,1.2) H4(-4.4,1.2) H5(-3.6,1.2) H6(-2.8,1.2) H7(-2,1.2) H8(-1.2,1.2) H9(-0.4,1.2) H10(0.4,1.2) H11(1.2,1.2) H12(2,1.2) H13(2.8,1.2) H14(3.6,1.2) H15(4.4,1.2) H16(5.2,1.2) H17(6,1.2) H18(6.8,1.2) J1(-6.8,0.4) J2(-6,0.4) J3(-5.2,0.4) J4(-4.4,0.4) J5(-3.6,0.4) J6(-2.8,0.4) J7(-2,0.4) J8(-1.2,0.4) J9(-0.4,0.4) J10(0.4,0.4) J11(1.2,0.4) J12(2,0.4) J13(2.8,0.4) J14(3.6,0.4) J15(4.4,0.4) J16(5.2,0.4) J17(6,0.4) J18(6.8,0.4) K1(-6.8,-0.4) K2(-6,-0.4) K3(-5.2,-0.4) K4(-4.4,-0.4) K5(-3.6,-0.4) K6(-2.8,-0.4) K7(-2,-0.4) K8(-1.2,-0.4) K9(-0.4,-0.4) K10(0.4,-0.4) K11(1.2,-0.4) K12(2,-0.4) K13(2.8,-0.4) K14(3.6,-0.4) K15(4.4,-0.4) K16(5.2,-0.4) K17(6,-0.4) K18(6.8,-0.4) L1(-6.8,-1.2) L2(-6,-1.2) L3(-5.2,-1.2) L4(-4.4,-1.2) L5(-3.6,-1.2) L6(-2.8,-1.2) L7(-2,-1.2) L8(-1.2,-1.2) L9(-0.4,-1.2) L10(0.4,-1.2) L11(1.2,-1.2) L12(2,-1.2) L13(2.8,-1.2) L14(3.6,-1.2) L15(4.4,-1.2) L16(5.2,-1.2) L17(6,-1.2) L18(6.8,-1.2) M1(-6.8,-2) M2(-6,-2) M3(-5.2,-2) M4(-4.4,-2) M5(-3.6,-2) M6(-2.8,-2) M7(-2,-2) M8(-1.2,-2) M9(-0.4,-2) M10(0.4,-2) M11(1.2,-2) M12(2,-2) M13(2.8,-2) M14(3.6,-2) M15(4.4,-2) M16(5.2,-2) M17(6,-2) M18(6.8,-2) N1(-6.8,-2.8) N2(-6,-2.8) N3(-5.2,-2.8) N4(-4.4,-2.8) N5(-3.6,-2.8) N6(-2.8,-2.8) N7(-2,-2.8) N8(-1.2,-2.8) N9(-0.4,-2.8) N10(0.4,-2.8) N11(1.2,-2.8) N12(2,-2.8) N13(2.8,-2.8) N14(3.6,-2.8) N15(4.4,-2.8) N16(5.2,-2.8) N17(6,-2.8) N18(6.8,-2.8) P1(-6.8,-3.6) P2(-6,-3.6) P3(-5.2,-3.6) P4(-4.4,-3.6) P5(-3.6,-3.6) P6(-2.8,-3.6) P7(-2,-3.6) P8(-1.2,-3.6) P9(-0.4,-3.6) P10(0.4,-3.6) P11(1.2,-3.6) P12(2,-3.6) P13(2.8,-3.6) P14(3.6,-3.6) P15(4.4,-3.6) P16(5.2,-3.6) P17(6,-3.6) P18(6.8,-3.6) R1(-6.8,-4.4) R2(-6,-4.4) R3(-5.2,-4.4) R4(-4.4,-4.4) R5(-3.6,-4.4) R6(-2.8,-4.4) R7(-2,-4.4) R8(-1.2,-4.4) R9(-0.4,-4.4) R10(0.4,-4.4) R11(1.2,-4.4) R12(2,-4.4) R13(2.8,-4.4) R14(3.6,-4.4) R15(4.4,-4.4) R16(5.2,-4.4) R17(6,-4.4) R18(6.8,-4.4) T1(-6.8,-5.2) T2(-6,-5.2) T3(-5.2,-5.2) T4(-4.4,-5.2) T5(-3.6,-5.2) T6(-2.8,-5.2) T7(-2,-5.2) T8(-1.2,-5.2) T9(-0.4,-5.2) T10(0.4,-5.2) T11(1.2,-5.2) T12(2,-5.2) T13(2.8,-5.2) T14(3.6,-5.2) T15(4.4,-5.2) T16(5.2,-5.2) T17(6,-5.2) T18(6.8,-5.2) U1(-6.8,-6) U2(-6,-6) U3(-5.2,-6) U4(-4.4,-6) U5(-3.6,-6) U6(-2.8,-6) U7(-2,-6) U8(-1.2,-6) U9(-0.4,-6) U10(0.4,-6) U11(1.2,-6) U12(2,-6) U13(2.8,-6) U14(3.6,-6) U15(4.4,-6) U16(5.2,-6) U17(6,-6) U18(6.8,-6) V1(-6.8,-6.8) V2(-6,-6.8) V3(-5.2,-6.8) V4(-4.4,-6.8) V5(-3.6,-6.8) V6(-2.8,-6.8) V7(-2,-6.8) V8(-1.2,-6.8) V9(-0.4,-6.8) V10(0.4,-6.8) V11(1.2,-6.8) V12(2,-6.8) V13(2.8,-6.8) V14(3.6,-6.8) V15(4.4,-6.8) V16(5.2,-6.8) V17(6,-6.8) V18(6.8,-6.8)
  silkscreen extent -8.27,-7.5 7.5,7.5, body extent -7.5,-7.5 7.5,7.5, height 1.5
"DR127 Series Inductor" [mm] "DR127 Series Inductor"
  rect 0.9x0.4 smd: 1(0.85,0.4) 2(-0.85,0.4) 3(-0.85,-0.4) 4(0.85,-0.4)
  silkscreen extent -1.48,-0.81 1.49,0.79, body extent -1.01,-0.64 1.01,0.65, height 1.64
HDR1X2 [mm] "Connector; Header; 2 Position"
  rect 1.5x1.5 hole 0.94: 1(0,0)
  round 1.5 hole 0.94: 2(2.54,0)
  silkscreen extent -1.27,-1.27 3.81,1.27
HDR1X3 [mm] "Connector; Header; 3 Position"
  rect 1.5x1.5 hole 0.94: 1(0,0)
  round 1.5 hole 0.94: 2(2.54,0) 3(5.08,0)
  silkscreen extent -1.27,-1.27 6.35,1.27
HDR1X6 [mm] "Connector; Header; 6 Position"
  rect 1.5x1.5 hole 0.94: 1(0,0)
  round 1.5 hole 0.94: 2(2.54,0) 3(5.08,0) 4(7.62,0) 5(10.16,0) 6(12.7,0)
  silkscreen extent -1.27,-1.27 13.97,1.27
MICRO-USB-B-RECEPTABLE [mm] "10118194-0001LF"
  rect 0.4x1.5 smd: 1(-1.3,1.2) 2(-0.65,1.2) 3(0,1.2) 4(0.65,1.2) 5(1.3,1.2)
  oval 1.1x2 hole 0.7 slot 1 at 90 deg: 6(2.225,1.4) 9(-2.225,1.4)
  rect 2.1x1.9 / inner round 1.3 / far side round 1.3 hole 1.2 slot 1.5 at 90 deg copper offset 0.1,0: 7(3.6,-1.4)
  rect 2.1x1.9 / inner round 1.3 / far side round 1.3 hole 1.2 slot 1.5 at 90 deg copper offset -0.1,0: 8(-3.6,-1.4)
  rect 1.8x1.8 smd: ""(-1.15,-1.4) ""(1.15,-1.4)
  silkscreen extent -4.53,-2.86 4.59,2.69, body extent -4.4,-4.29 4.25,1.61, height 2.85
"PIN HEADER 1X2 PIN IN PASTE" [mm] "Pin header 1x2 Pin in Paste"
  rect 0.8x1 hole 0.6: 1(0,0)
  oval 0.8x1 hole 0.6: 2(1.27,0)
  silkscreen extent -0.76,-0.89 2.03,0.89
QFN32_5X5MM_EP3P3MM [mil] "QFN32_5X5MM_EP3P3MM"
  oval 10x33 smd mask+2: 1(-68.95,-99) 8(68.95,-99) 17(68.95,99) 24(-68.95,99)
  rect 10x33 smd mask+2: 2(-49.25,-99) 3(-29.55,-99) 4(-9.85,-99) 5(9.85,-99) 6(29.55,-99) 7(49.25,-99) 18(49.25,99) 19(29.55,99) 20(9.85,99) 21(-9.85,99) 22(-29.55,99) 23(-49.25,99)
  oval 33x10 smd mask+2: 9(99,-68.95) 16(99,68.95) 25(-99,68.95) 32(-99,-68.95)
  rect 33x10 smd mask+2: 10(99,-49.25) 11(99,-29.55) 12(99,-9.85) 13(99,9.85) 14(99,29.55) 15(99,49.25) 26(-99,49.25) 27(-99,29.55) 28(-99,9.85) 29(-99,-9.85) 30(-99,-29.55) 31(-99,-49.25)
  rect 129.92x129.92 smd mask+2: 33(0,0)
  silkscreen extent -113,-137 101,101
SMA [mm] "SMA card edge mount 1.6mm substrate"
  rect 3.6x1.8 smd: 1(0,0)
  rect 4.2x1.35 hole 0.8 paste-0.3: 2(-0.3,-2.825)
  rect 4.2x1.35 hole 0.8 paste-0.3 mask+0: 2.1(-0.3,2.825)
  silkscreen extent -2,-3.95 3.15,3.92, body extent -12.17,-3.18 1.16,3.18, height 3.71
SO8 [mm] "SOIC, 8-Leads, Body 4.9x3.9mm, Pitch 1.27mm, IPC Low Density"
  rect 1.5x0.65 smd: 1(0,0) 2(0,-1.27) 3(0,-2.54) 4(0,-3.81) 5(5.5,-3.81) 6(5.5,-2.54) 7(5.5,-1.27) 8(5.5,0)
  silkscreen extent 0.08,-4.48 3.89,1.01, body extent -0.31,-4.4 5.89,0.6, height 1.75
"so8exposed pad" [mm]
  rect 0.8x2.2 smd: 1(-1.905,-2.87) 2(-0.635,-2.87) 3(0.635,-2.87) 4(1.905,-2.87) 5(1.905,2.87) 6(0.635,2.87) 7(-0.635,2.87) 8(-1.905,2.87)
  rect 3.81x2.7 smd: 9(0,0)
  silkscreen extent -2.67,-3.48 -2.67,-2.62
SOT23-5 [mm]
  rect 0.7x1.1 smd: 1(-0.95,-1.3) 2(0,-1.3) 3(0.95,-1.3) 4(0.95,1.3) 5(-0.95,1.3)
  silkscreen extent -1.52,-2.13 1.63,2.08, body extent -1.48,-1.6 1.52,1.6, height 0.92
sot23-6 [mm]
  rect 0.85x0.35 smd: 1(-0.925,0.65) 2(-0.925,0) 3(-0.925,-0.65) 4(0.925,-0.65) 5(0.925,0) 6(0.925,0.65)
  silkscreen extent -1.6,-1.35 1.6,1.35, body extent -1.05,-1 1.05,1, height 0.95
"SOT23-6 - duplicate" [mm] "SOT23, 6-Leads, Body 2.9x1.6mm, Pitch 0.95mm, Lead Span 2.7mm, IPC High Density"
  rect 1.2x0.6 smd: 1(-1.2,0.95) 2(-1.2,0) 3(-1.2,-0.95) 4(1.2,-0.95) 5(1.2,0) 6(1.2,0.95)
  silkscreen extent -1.33,-1.55 0.3,1.95, body extent -1.42,-1.46 1.42,1.46, height 1.25
SOT143 [mm]
  rect 1.2x1 smd: 1(-0.75,-0.9)
  rect 0.9x1 smd: 2(0.95,-0.9) 3(0.95,0.9) 4(-0.95,0.9)
  silkscreen extent -1.88,-1.91 1.83,1.65
"Testpad 29 mil" [mil] "Testpad 29 mil"
  round 29 smd paste-25: 1(0,0)
uDFN-6 [mm] "uDFN-6"
  rect 1.7x0.95 smd mask+0.051: 0(0,-0.001)
  rect 0.4x0.47 smd mask+0.051: 1(-0.65,-0.915) 2(0,-0.915) 3(0.65,-0.915) 4(0.65,0.915) 5(0,0.915) 6(-0.65,0.915)
  body extent -1,-1.02 1,0.99, height 0.75

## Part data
B1 B1A: "2.45 GHz Balun / Filter Combination"
C1 C1A C9 C11 C13 C13A C14 C14A C15 C15A C16 C16A C17 C17A C110: library part A01-0246, "Ceramic capacitor, SMD 0402, X7R, 16V, +/-10%"
C001: "Polarized Capacitor (Radial)"
C01 C002 C49 C50 C51 C52 C53 C54 C55 C56 C57 C58 C59 C60 C61 C62 C63 C64 C65 C66 C67 C68: library part CAP-NONPOL, "Ceramic capacitor, SMD 0402, X5R, 6.3V, +/-20% (de33687)"
C2 C02A C12 C12A: library part A01-0682, "CAP CER 1.8PF 25V NP0 0201"
C3 C3A: library part A01-0683, "CAP CER 0.8PF 25V NP0 0201"
C4 C4A C21 C21A: library part A01-0612, "Ceramic Capacitor, SMD 0201, 25V, NP0, 1.2pF"
C5 C5A: library part A01-0681, "CAP CER 8.2PF 25V NP0 0201"
C7 C7A C22 C22A: library part A01-0472, "CAP CER 2.2PF 6.3V NP0 0201"
C8 C08A: library part A01-0611, "CAP CER 15PF 25V NP0 0201"
C10 C10A: library part A01-0581, "CAP CER 10PF 25V ±.25pf ( and ±.30ppm/ degree C of temp variation) NP0 0201"
C18 C18A C19 C19A C20 C20A: library part A01-0286, "Ceramic capacitor, SMD 0402, X5R, 6.3V, +/-10% (de26942)"
C23 C230: library part A01-0276, "Ceramic capacitor, SMD 1206, X5R, 6.3V, ±10%"
C24 C24A C024A: library part A01-0351, "Ceramic capacitor, SMD 0402, NP0, 50V, +/-0.25pF (de23847)"
C25 C25A: library part A01-0577, "Ceramic capacitor, SMD 0201, X7R, 10V, +/-10%"
C26 C27 C31 C32: library part CAP-NONPOL_1, "Ceramic capacitor, SMD 1206, X5R, 6.3V, ±10%"
C28 C33: library part CAP-NONPOL_1
C29 C30 C34 C35 C41 C42 C43 C44 C45 C46 C47 C48: library part CAP-NONPOL_2
C69 C70 C71 C72 C73 C74 C75 C76 C77 C78 C79 C80 C81 C82: library part CAP-NONPOL
C85 C86 C87 C88 C89 C90 C91 C92 C93 C94 C95 C96 C97: library part CAP-NONPOL_3, "Ceramic capacitor, SMD 0201, X7R, 10V, +/-10%"
D1 D1A: library part A10-0018, "LED, Green, Wave length=575nm, SMD 0805, ±70°"
D001 DA DB DC DD: "Schottky Diode"
D2 D2A: library part A10-0019, "LED, Yellow, Wave length=591nm, SMD 0805, ±70°"
D2A1: "Typical INFRARED GaAs LED"
IC2 IC2A: "IC EEPROM 2KBIT 1MHz, 1.7V to 5.5V, SOT23-5"
IC7 IC7A: "Sub-1GHz/2.4GHz Transceiver"
IC8: "1:2 FANOUT BUFFER IC"
J1 J10 J104 J104A J105 J105A JP: library part A08-1754, "1x2 pin header, 2.54mm pitch, Pin-in-Paste THM"
JP1: "Header, 3-Pin"
L1 L1A: library part A03-0131, "Sub-1GHz Balun"
L2 L20: library part A03-0072, "SMD-Ferrite 220Ohm, 100MHz 0603 size, (de14411)"
L3 L3A: library part A03-0150
L4 L5 L7 L8: library part INDUCTOR
P1A: library part A08-0838, "UFL (Small Coax Connector)"
P4: library part "Header 2", "Header, 2-Pin"
P-ADC: "Header, 10-Pin, Dual row, Right Angle"
Pio: library part "Header 20", "Header, 20-Pin"
Q1 Q10: library part A05-0051, "Dual N-Channel MOSFET, 60V, 115mA cont,RDS(ON) < 7.5 Ohm @50mA@5V, SOT-363"
R1 R1A R5 R5A: library part A02-0284, "Thick film resistor, SMD 0402, 1/16W, 1%"
R001 R002 R018 R019 R032: "Thick film resistor, SMD 0402, 1/16W, 1%"
R2 R2A R3 R3A: library part A02-0200, "Thick film resistor, SMD 0402, 1/16W, 1%"
R4 R4A R9 R9A: library part A02-0553, "Thick film resistor, SMD 0201, 1/20W, 5%"
R7 R7A: library part A02-0677, "RES 100K OHM 1/20W 5% 0201 SMD"
R10 R10A R11 R11A R13 R13A: library part A02-0541, "Thick film resistor, SMD 0201, 1/20W, 5%"
R12 R12A: library part A02-0196, "Thick film resistor, SMD 0402, 1/16W, 1%"
R14 R015 R16 R17 R18 R19 R23 R24 R25 R26 R27: library part R2_1, "Thick film resistor, SMD 0201, 1/20W, 5%"
R15B R40 R41 R42 R43 R44 R45 R46 R47 R48 R49 R50 R51 R53 R54 R55 R56 R57 R58 R60 R61 R62 R63 R64 R65 R72 R73 R74 R75 R76 R77 R78 R79: "Resistor"
R66 R67 R68 R69 R70 R71: library part Res1, "Resistor"
R101 R101A R102 R102A: library part A02-0236, "Thick film resistor, SMD 0402, 1/16W, 1%"
R144 R145 R146 R147: library part R2, "Thick film resistor, SMD 0402, 1/16W, 1%"
SMA1 SMA2 SMA3 SMA4: library part A08-1047, "End Launch Jack Receptacle, Round Contact (de21535)"
TP1 TP1A TP2 TP2A TP10 TP10A TP11 TP11A TP12 TP12A TP13 TP13A: library part A08-0892, "Single SMD testpad"
TP8 TP9: library part A08-1716, "THM Test Point, Without Base, 1.0mm Dia. Mounting"
U5: library part RT8288AZSP, "IC REG BUCK ADJ 4A SYNC 8SOP"
U06: library part SC189SKTRT, "IC REG BUCK 1.8V 1.5A SYNC SOT23"
U6: "Artix-7 FPGA, 210 User I/Os, 0 GTP, 324-Ball BGA, Speed Grade 2, Industrial Grade, Pb-Free"
U8: library part XC2C32A-6QFG32C, "IC CPLD 32MC 5.5NS 32QFN"
U9: library part S25FL127SABMFI101, "IC FLASH 128MBIT 108MHZ 8SOIC"
U10: "EZ-USB FX2LP USB Microcontroller Ideal for Battery Powered Applications,16K RAM, 40 I/Os, 100-Pin TQFP, Pb-Free, Commercial Grade"
U11: library part "UP SUPERVISORY"
U12: library part 24LC128SN
W1 W2: "Jumper Wire"
XC1: library part A07-0087, "26MHz TCXO, 2.8 ~ 3.3V, Clipped sine wave 10KOhm/10pF, 3.2 x 2.5 mm SMD"
XC2: library part "ACT33T-4 TCXO"
XL1: library part "ACT33T-4 TCXO_1", "26MHz TCXO, 2.8 ~ 3.3V, Clipped sine wave 10KOhm/10pF, 3.2 x 2.5 mm SMD"

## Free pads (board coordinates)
  round 137.8 hole 78.74: 0(3814,96.67) 1(3830.12,2512) 2(1677,2519.69) 3(108.06,2506) 4(107,100.69)

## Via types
v1: diameter 20, hole 10, Top Layer LF-signals to Bottom Layer LF-signals, 660 vias
v2: diameter 14, hole 6, Top Layer LF-signals to Bottom Layer LF-signals, 470 vias
v3: diameter 40, hole 20, Top Layer LF-signals to Bottom Layer LF-signals, 46 vias
v4: diameter 12, hole 6, Top Layer LF-signals to Bottom Layer LF-signals, 1 vias

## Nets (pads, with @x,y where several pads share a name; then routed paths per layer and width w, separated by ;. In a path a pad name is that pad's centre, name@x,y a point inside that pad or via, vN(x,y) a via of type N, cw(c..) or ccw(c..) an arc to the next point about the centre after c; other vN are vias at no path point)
1V0: C43.1 C44.1 C45.1 C55.1 C56.1 C57.1 C58.1 C59.1 C60.1 C61.1 C62.1 L7.2 R24.1 U6.F8 U6.F10 U6.G7 U6.G9 U6.G11 U6.H8 U6.J7 U6.J11 U6.K8 U6.L7 U6.L11 U6.M8 U6.M10 U6.N7 U6.N9 U6.N11 | length 7937
  Top Layer LF-signals w5: v2@2114,1418 v2@2114,1419.33 ; U6.J11@2123.67,1303.02 2124.98,1303.02 U6.J11@2127.23,1303.02 ; v2(2139,1163) 2139.42,1163.42 2139.42,1192.79 U6.F10@2155.17,1208.54 ; v2(2139,1289) v2@2139,1291.26 ; U6.M10@2155.17,1395.33 U6.M10@2155.17,1397.51 ; v2(2176.66,1419) U6.N9@2186.67,1429.01 ; v2(2197.23,1254.1) 2200.73,1254.1 U6.H8@2218.16,1271.53 ; U6.K8@2213.97,1334.52 U6.K8@2218.16,1334.52 ; v2(2236.63,1227) U6.G7@2249.66,1240.03
  Top Layer LF-signals w7: v2@2114,1418 2123.67,1427.67 U6.N11@2123.67,1429.01 ; U6.L11@2123.67,1366.02 v2(2136.49,1378.83) ; U6.J11@2124.98,1303.02 v2(2139,1289) ; U6.M10@2155.17,1397.51 2166,1386.68 v2(2166,1387) ; v2(2194,1416) 2212.49,1397.51 U6.M8@2218.16,1397.51 U6.N7@2249.66,1429.01 ; v2(2208,1345) 2211,1345 2218.16,1337.84 U6.K8@2218.16,1334.52 U6.L7@2249.66,1366.02
  Top Layer LF-signals w8: U6.G11@2123.67,1240.03 U6.F10@2155.17,1208.54 ; U6.G9@2186.67,1240.03 2186.67,1243.53 v2(2197.23,1254.1) ; U6.F8@2218.16,1208.54 v2(2236.63,1227) ; U6.K8@2218.16,1334.52 U6.J7@2249.66,1303.02
  Bottom Layer LF-signals w8: v2@2114,1418 2114,1378 2139,1353 v2(2139,1289) ; v2(2136.49,1378.83) 2148.99,1366.33 2186.67,1366.33 2194.34,1374 2345,1374 2379,1340 2432,1340 2445.38,1326.62 2534.9,1326.62 2551.19,1342.91 2590.34,1342.91 C59.1@2598,1335.24 ; v2(2139,1163) 2310,992 2560,992 C57.1@2598,1030 ; v2(2166,1387) 2166,1386.68 2169.51,1383.17 2411.83,1383.17 2452.09,1342.91 2503.91,1342.91 2530.87,1369.87 C58.1@2598,1369.87 ; v2(2176.66,1419) 2176.66,1407.52 2192.18,1392 2424.25,1392 2432.99,1400.74 2544.74,1400.74 2559.42,1415.42 C55.1@2598,1415.42 ; v2(2194,1416) 2202,1408 2361.59,1408 2420.19,1466.6 C56.1@2598,1466.6 ; v2(2197.23,1254.1) 2207.19,1254.1 2223,1269.91 2241.51,1269.91 2339.51,1171.91 2362,1171.91 2384.91,1149 2489.65,1149 2529.49,1109.15 C62.1@2598,1109.15 ; v2(2208,1345) 2211,1345 2249,1307 2521.81,1307 2543.4,1285.41 C61.1@2598,1285.41 ; v2(2236.63,1227) 2236.63,1206.78 2252.09,1191.31 2252.09,1190 2262,1180.1 2263.31,1180.1 2275.09,1168.31 2275.09,1148 2360,1063.1 2598,1063.1 C60.1@2598,1064.74
  Bottom Layer LF-signals w12: v2@2114,1418 v2(2114,1421) 2114,1487.33 2155.67,1529 2574.51,1529 2598,1505.51 C56.1@2598,1466.6
  Bottom Layer LF-signals w20: L7.2@89,393.37 94.34,393.37 183.97,483 688.37,483 C45.1@833.37,338 ; C62.1@2598,1109.15 C62.1@2598,1111.96 ; C61.1@2598,1285.41 C59.1@2598,1335.24 C58.1@2598,1369.87 C55.1@2598,1415.42 C56.1@2598,1466.6
  Bottom Layer LF-signals w40: 986,348 1081.57,348 1421.57,688 2390.51,688 2594,891.49 2594,1014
